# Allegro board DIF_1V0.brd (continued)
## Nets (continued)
IO_PRE_3.3_1: R160.2 U3.R2(IO_L3N_T0_DQS_34)
IO_PRE_3.3_2: R158.1 U3.R3(IO_L3P_T0_DQS_34)
IO_PRE_3.3_3: R156.2 U3.R4(IO_L13P_T2_MRCC_34)
IO_PRE_3.3_4: R154.1 U3.T4(IO_L13N_T2_MRCC_34)
IO_PRE_3.3_5: R152.2 U3.T1(IO_L1P_T0_34)
IO_PRE_3.3_6: R150.1 U3.T3(IO_0_34)
IO_PRE_3.3_7: R148.2 U3.U1(IO_L1N_T0_34)
IO_PRE_3.3_8: R146.1 U3.U3(IO_L6P_T0_34)
IO_PRE_3.3_9: R144.2 U3.Y1(IO_L5N_T0_34)
IO_PRE_3.3_10: R138.1 U3.V3(IO_L6N_T0_VREF_34)
IO_PRE_3.3_11: R111.2 U3.Y2(IO_L4N_T0_34)
IO_PRE_3.3_12: R118.1 U3.V5(IO_L16N_T2_34)
IO_PRE_3.3_13: R130.1 U3.V4(IO_L12P_T1_MRCC_34)
IO_PRE_3.3_14: R132.2 U3.V2(IO_L2N_T0_34)
IO_PRE_3.3_15: R134.1 U3.W1(IO_L5P_T0_34)
IO_SMA1: R19.2 U3.B21(IO_L21P_T3_DQS_16)
IO_SMA2: R26.2 U3.A21(IO_L21N_T3_DQS_16)
IO_SMA3: R30.2 U3.B15(IO_L7P_T1_16)
IO_SMA4: R28.2 U3.G13(IO_L1N_T0_AD0N_15)
IO_SMA5: R32.2 U3.G15(IO_L2P_T0_AD8P_15)
M2: J8.2 U3.U9(M2_0)
OUT_CK_5N_1: R69.1 R70.1 R81.2
OUT_CK_5P_1: R68.2 R69.2 R79.2
OUT_CK_40N_1: R97.1 R108.1 R115.1
OUT_CK_40P_1: R84.1 R95.2 R108.2
OUT_DATA_2+: U8.2(TX1_P) U8.14(TX2_P) U10.2(1Y)
OUT_DATA_2-: U8.3(TX1_N) U8.15(TX2_N) U10.3(1Z)
OUT_DATA_3+: U8.11(RX2_P) U8.23(RX1_P) U10.6(2Y)
OUT_DATA_3-: U8.10(RX2_N) U8.22(RX1_N) U10.5(2Z)
OUT_DATA_4+: U9.6(D_P A) U9.18(D_P B) U10.10(3Y)
OUT_DATA_4-: U9.7(D_N A) U9.19(D_N B) U10.11(3Z)
OUT_RAZ_CHN_N_1: R85.1 R90.1 R93.2
OUT_RAZ_CHN_P_1: R82.2 R85.2 R102.2
OUT_RX_HV: U3.AA5(IO_L10P_T1_34) U6.3(RXD)
OUT_TRIG_EXT_N_1: R75.1 R76.1 R101.1
OUT_TRIG_EXT_P_1: R74.2 R75.2 R89.1
OUT_VAL_EVT_N_1: R72.1 R73.1 R88.2
OUT_VAL_EVT_P_1: R71.2 R72.2 R98.2
PROGRAM_B: R43.1 SW2.2 U3.N12(PROGRAM_B_0)
REFCLK+: C1.1 O1.4(OUT+) R1.1
REFCLK-: C5.1 O1.5(OUT-) R1.2
RESET#: C115.1 R65.1 U12.49(RESETN) U15.2
RX_VCCP_0: C128.1 C129.1 C130.1 DU1.15(VCCR) L5.1
SCL: R63.1 U12.22(SCL) U14.6(SCL)
SDA: R64.1 U12.23(SDA) U14.5(SDA)
SFP_RS0: DR14.1 DR15.1 DU1.7(RS0)
SFP_RS1: DR12.1 DR13.1 DU1.9(RS1)
TRG_EXT: R22.2 U3.A13(IO_L10P_T1_16)
TX_VCCP_0: C121.1 C122.1 C123.1 DU1.16(VCCT) L4.1
USB_CLKOUT: R52.1 U3.Y18(IO_L13P_T2_MRCC_14)
USB_FD0: U3.W22(IO_L7N_T1_D10_14) U12.25(PB0/FD0)
USB_FD1: U3.T21(IO_L4P_T0_D04_14) U12.26(PB1/FD1)
USB_FD2: U3.R17(IO_L24N_T3_A00_D16_14) U12.27(PB2/FD2)
USB_FD3: U3.P16(IO_L24P_T3_A01_D17_14) U12.28(PB3/FD3)
USB_FD4: U3.T18(IO_L20N_T3_A07_D23_14) U12.29(PB4/FD4)
USB_FD5: U3.R18(IO_L20P_T3_A08_D24_14) U12.30(PB5/FD5)
USB_FD6: U3.U21(IO_L4N_T0_D05_14) U12.31(PB6/FD6)
USB_FD7: U3.U18(IO_L18N_T2_A11_D27_14) U12.32(PB7/FD7)
USB_FD8: U3.AB20(IO_L15N_T2_DQS_DOUT_CSO_B_14) U12.52(PD0/FD8)
USB_FD9: U3.AA19(IO_L15P_T2_DQS_RDWR_B_14) U12.53(PD1/FD9)
USB_FD10: U3.AA18(IO_L17P_T2_A14_D30_14) U12.54(PD2/FD10)
USB_FD11: U3.AB18(IO_L17N_T2_A13_D29_14) U12.55(PD3/FD11)
USB_FD12: U3.V17(IO_L16P_T2_CSI_B_14) U12.56(PD4/FD12)
USB_FD13: U3.W17(IO_L16N_T2_A15_D31_14) U12.1(PD5/FD13)
USB_FD14: U3.U17(IO_L18P_T2_A12_D28_14) U12.2(PD6/FD14)
USB_FD15: U3.R16(IO_L22N_T3_A04_D20_14) U12.3(PD7/FD15)
USB_FLAGA: U3.V20(IO_L11N_T1_SRCC_14) U12.36(CTL0/FLAGA)
USB_FLAGB: U3.W20(IO_L12N_T1_MRCC_14) U12.37(CTL1/FLAGB)
USB_FLAGC: R55.2 U3.W21(IO_L7P_T1_D09_14)
USB_FLAGD/SLCS#: U3.Y19(IO_L13N_T2_MRCC_14) U12.47(PA7/FLAGD/SLCSN)
USB_IFCLK: U3.Y22(IO_L9N_T1_DQS_D13_14) U12.20(IFCLK)
USB_PKTEND: U3.AB21(IO_L10P_T1_D14_14) U12.46(PA6/PKTEND)
USB_SLOE: R58.2 U3.Y21(IO_L9P_T1_DQS_14)
USB_SLRD: U3.AB22(IO_L10N_T1_D15_14) U12.8(RDY0/*SLRD)
USB_SLWR: R59.2 U3.W19(IO_L12P_T1_MRCC_14)
USB_WAKEUP: R56.1 U3.AA20(IO_L8P_T1_D11_14)
USB_WU2: R57.1 U3.V19(IO_L14N_T2_SRCC_14)
WU: J13.2 R56.2 U12.51(WAKEUP)
WU2_S: J14.2 R57.2 U12.43(PA3/WU2)
XTALIN: C107.2 U12.12(XTALIN) Y1.1
XTALOUT: C106.2 U12.11(XTALOUT) Y1.2
N00327: C102.1 R48.1 U6.10(VO)
N00500: R49.2 U6.16(TEMP)
N00677: R50.2 U7.3(OUT)
N00715: C105.1 R51.2 U7.4(VDD)
N12323: J7.4(TMS) R38.1
N12327: R38.2 U3.T13(TMS_0)
N12331: R39.2 U3.V12(TCK_0)
N12335: R40.2 U3.U13(TDO_0)
N12339: R41.2 U3.R13(TDI_0)
N12343: J7.6(TCK) R39.1
N12347: J7.8(TDO) R40.1
N12351: J7.10(TDI) R41.1
N12485: U3.AB17(IO_L2N_T0_13) U11.3(DO1)
N12489: U3.AA16(IO_L1N_T0_13) U11.5(DO2)
N12493: U3.AB16(IO_L2P_T0_13) U11.11(DO3)
N12742: U3.AA14(IO_L5N_T0_13) U10.1(1A)
N12746: U3.AB15(IO_L4N_T0_13) U10.7(2A)
N12750: U3.AA15(IO_L4P_T0_13) U10.9(3A)
N13183: D9.1(CATHODE) R47.2
N13221: D10.2(ANODE) R46.1
N15768: DR2.1 DR16.1 DU1.3(TX_DISABLE) U3.A14(IO_L10N_T1_16)
N15772: D12.1(CATHODE) DR1.1 DU1.2(TX_FAULT) U3.B16(IO_L7N_T1_16)
N15776: DR5.1 DU1.4(SDA) U3.B17(IO_L11P_T1_SRCC_16)
N15834: DR6.1 DU1.5(SCL) U3.B13(IO_L8N_T1_16)
N15838: D14.1(CATHODE) DR4.1 DU1.8(LOS) U3.A18(IO_L17P_T2_16)
N16065: C126.2 R66.1 U3.B8(MGTPRXP0_216)
N16069: C120.2 R66.2 U3.A8(MGTPRXN0_216)
N16073: C127.1 U3.B4(MGTPTXP0_216)
N16077: C133.1 U3.A4(MGTPTXN0_216)
N17024: R34.2 U3.F8(MGTRREF_216)
N26834: R114.2 U3.N4(IO_L19P_T3_35)
N27061: R117.1 U3.M5(IO_L23N_T3_35)
N27703: R110.2 U3.N3(IO_L19N_T3_VREF_35)
N27930: R112.1 U3.M2(IO_L16N_T2_35)
N28287: R107.1 U3.N2(IO_L22N_T3_35)
N29233: R123.2 U3.K4(IO_L13P_T2_MRCC_35)
N29237: R125.1 U3.K3(IO_L14N_T2_SRCC_35)
N31078: R71.1 U3.K1(IO_L7P_T1_AD6P_35)
N31082: R73.2 U3.J1(IO_L7N_T1_AD6N_35)
N31695: R68.1 U3.R1(IO_L20P_T3_35)
N31699: R70.2 U3.P1(IO_L20N_T3_35)
N31992: R95.1 U3.M1(IO_L15P_T2_DQS_35)
N31996: R115.2 U3.L1(IO_L15N_T2_DQS_35)
N32289: R74.1 U3.H2(IO_L8P_T1_AD14P_35)
N32293: R76.2 U3.G2(IO_L8N_T1_AD14N_35)
N33117: R82.1 U3.G1(IO_L5P_T0_AD13P_35)
N33121: R90.2 U3.F1(IO_L5N_T0_AD13N_35)
N33886: R105.2 U3.P4(IO_L21N_T3_DQS_35)
N33890: R94.1 U3.P2(IO_L22P_T3_35)
N34550: R91.1 U3.Y7(IO_L23N_T3_34)
N34554: R100.2 U3.AA4(IO_L11N_T1_SRCC_34)
N36552: R96.1 U3.W5(IO_L15N_T2_DQS_34)
N36779: R106.2 U3.AB2(IO_L8N_T1_34)
N37008: R109.1 U3.W6(IO_L15P_T2_DQS_34)
N38396: R104.2 U3.AA3(IO_L9N_T1_DQS_34)
N38400: R103.1 U3.Y6(IO_L18P_T2_34)
N38404: R92.2 U3.AB3(IO_L8P_T1_34)
N38635: R99.1 U3.W7(IO_L19N_T3_VREF_34)
N38992: R87.2 U3.AA6(IO_L18N_T2_34)
N39253: R83.2 U3.AB8(IO_L22N_T3_34)
N39482: R80.1 U3.Y8(IO_L23P_T3_34)
N39711: R78.2 U3.Y9(IO_L24N_T3_34)
N39940: R77.1 U3.W9(IO_L24P_T3_34)
N40729: R113.1 U3.Y4(IO_L11P_T1_SRCC_34)
N40733: R116.2 U3.U5(IO_L14N_T2_SRCC_34)
N41303: R128.2 U3.W2(IO_L4P_T0_34)
N42028: R126.1 U3.AB1(IO_L7N_T1_34)
N42251: R124.2 U3.AA1(IO_L7P_T1_34)
N42476: R120.2 U3.Y3(IO_L9P_T1_DQS_34)
N42480: R122.1 U3.W4(IO_L12N_T1_MRCC_34)
N63573: C5.2 R2.2 U3.E6(MGTREFCLK0N_216)
N64906: C103.1 R48.2 R145.1 R147.2 TP10.1
N64910: C104.1 R49.1 R50.1 R142.1
N65349: C1.2 R2.1 U3.F6(MGTREFCLK0P_216)
N65361: R4.2 U3.U20(IO_L11P_T1_SRCC_14)
N65373: R6.2 R8.1 U3.D19(IO_L14N_T2_SRCC_16)
N71766: R127.2 U3.L4(IO_L18N_T2_35)
N72632: R141.1 U3.J4(IO_L13N_T2_MRCC_35)
N73220: R119.2 U3.M3(IO_L16P_T2_35)
N73812: R86.1 U3.AA8(IO_L22P_T3_34)
N179918: R163.2 R165.1 U16.16(FB/SNS)
N180887: R170.2 R172.1 U19.16(FB/SNS)
N181938: R181.2 R183.1 U20.16(FB/SNS)
N182899: R164.2 R166.1 U17.16(FB/SNS)
N183888: R171.2 R173.1 U18.16(FB/SNS)
N606190: C3.2 C4.2 L1.2 U1.4(VCC)
N606320: R4.1 U1.3(OUT)
N607489: R9.1 U2.4(PFI)
N607623: R5.1 SW1.2 U2.1(/MR)
N607665: R8.2 R10.2 U2.7(/RESET)
N1798468: R167.1 U16.9(PG)
N1808198: R174.1 U19.9(PG)
N1818788: R186.1 U20.9(PG)
N1828438: R168.1 U17.9(PG)
N1838328: R175.1 U18.9(PG)
N15089767: O1.1(ST/OE) R3.1
N15104211: J8.3 R42.2
N15135333: D1.2(ANODE) R11.2
N15135363: D2.2(ANODE) R12.2
N15135433: D3.2(ANODE) R13.2
N15135465: D4.2(ANODE) R14.2
N15135513: D5.2(ANODE) R15.2
N15135593: D6.2(ANODE) R16.2
N15135681: D7.2(ANODE) R17.2
N15135745: D8.2(ANODE) R18.2
N15136939: J2.1 R21.1 R23.1
N15136999: R21.2 U4.3(VP)
N15137097: R24.1 R25.1 U4.4(VN)
N15137609: J1.1 R19.1 R20.1
N15137848: J3.1 R26.1 R27.1
N15138095: J5.1 R30.1 R31.1
N15138348: J4.1 R28.1 R29.1
N15138605: J6.1 R32.1 R33.1
N16764512: R190.2 R191.1 U21.16(FB/SNS)
N16766730: D18.2(ANODE) R185.2
N16766909: D19.2(ANODE) R187.2
N16767511: D21.2(ANODE) R189.2
N16767909: D17.2(ANODE) R184.2
N16777633: R52.2 U12.5(CLKOUT)
N16778120: J15.2 R62.1 U14.1(A0)
N16778188: U12.16(DMINUS) U13.2(D-)
N16778190: U12.15(DPLUS) U13.3(D+)
N16778248: R53.2 U12.21(RESERVED)
N16778864: D16.1(ANODE) R194.2
N16779811: DR12.2 DR17.2
N16779911: DR14.2 DR18.2
N16782519: D11.1(ANODE) R54.1
N16783572: J16.B2 R78.1
N16783577: J16.B4 R83.1
N16783581: J16.B6 R87.1
N16783585: J16.B8 R100.1
N16783590: J16.B10 R92.1
N16783594: J16.B12 R104.1
N16783598: J16.B14 R106.1
N16783603: J16.B16 R111.1
N16783607: J16.B18 R116.1
N16783611: J16.B20 R120.1
N16783616: J16.B22 R124.1
N16783620: J16.B24 R128.1
N16783624: J16.B26 R132.1
N16783629: J16.B28 R136.1
N16783633: J16.B30 R140.1
N16783637: J16.B32 R144.1
N16783642: J16.B34 R148.1
N16783646: J16.B36 R152.1
N16783650: J16.B38 R156.1
N16783654: J16.B40 R160.1
N16789956: J17.A3 R84.2
N16789966: J17.A7 R89.2
N16789976: J17.A11 R94.2
N16789981: J17.A13 R107.2
N16789986: J17.A15 R112.2
N16789991: J17.A17 R117.2
N16789996: J17.A19 R121.2
N16790001: J17.A21 R125.2
N16790006: J17.A23 R129.2
N16790016: J17.A27 R137.2
N16790021: J17.A29 R141.2
N16790026: J17.A31 R145.2
N16790031: J17.A33 R149.2
N16790036: J17.A35 R153.2
N16790041: J17.A37 R157.2
N16790052: J17.A39 R161.2
N16790060: J17.B2 R81.1
N16790070: J17.B6 R88.1
N16790080: J17.B10 R93.1
N16790085: J17.B12 R105.1
N16790090: J17.B14 R110.1
N16790095: J17.B16 R114.1
N16790100: J17.B18 R119.1
N16790105: J17.B20 R123.1
N16790110: J17.B22 R127.1
N16790120: J17.B26 R135.1
N16790130: J17.B30 R143.1
N16790135: J17.B32 R147.1
N16790140: J17.B34 R151.1
N16790145: J17.B36 R155.1
N16790150: J17.B38 R159.1
N16790155: J17.B40 R162.1
N16838243: J17.A4 R97.2
N16838862: J17.B5 R98.1
N16839386: J17.A8 R101.2
N16839910: J17.B9 R102.1
N16840818: J17.A26 R139.2
N16841427: J17.B25 R133.1
N16841941: J17.A24 R131.2
N17984614: C140.1 U16.15(SS)
N18081914: C148.1 U19.15(SS)
N18187814: C157.1 U20.15(SS)
N18284314: C141.1 U17.15(SS)
N18383214: C149.1 U18.15(SS)
N151370452: R22.1 U4.1(Q)
N167617330: J18.1 R178.1
N167617332: J18.3 R179.1
N167644448: R192.1 U21.9(PG)
N167671021: D20.2(ANODE) R188.2
N167776730: R55.1 U12.38(CTL2/FLAGC)
N167776810: R58.1 U12.42(PA2/SLOE)
N167776910: R59.1 U12.9(RDY1/*SLWR)
N167800060: D12.2(ANODE) DR9.1
N167800300: D13.2(ANODE) DR10.1
N167800460: D14.2(ANODE) DR11.1
N167801340: DR7.1
N167801341: DR8.1
N167815100: R54.2 U13.1(V)
N167837560: J16.A1 R77.2
N167837562: J16.A3 R80.2
N167837564: J16.A5 R86.2
N167837566: J16.A7 R99.2
N167837568: J16.A9 R91.2
N168028960: J13.1 R60.1
N168030100: J14.1 R61.1
N1676444414: C161.1 U21.15(SS)
N1678375610: J16.A11 R103.2
N1678375612: J16.A13 R96.2
N1678375614: J16.A15 R109.2
N1678375616: J16.A17 R113.2
N1678375618: J16.A19 R118.2
N1678375620: J16.A21 R122.2
N1678375622: J16.A23 R126.2
N1678375624: J16.A25 R130.2
N1678375626: J16.A27 R134.2
N1678375628: J16.A29 R138.2
N1678375630: J16.A31 R142.2
N1678375632: J16.A33 R146.2
N1678375634: J16.A35 R150.2
N1678375636: J16.A37 R154.2
N1678375638: J16.A39 R158.2
N1679025740: J17.B1 R79.1

Pads without a net: J7 12 14; O1 2; U1 1; U2 5 6 8; U3 A6 A10 A15 A16 A19 AA9 AA10 AA11 AA13 AB6 AB7 AB10 AB11 AB12 AB13 B6 B10 B18 B20 B22 C5 C7 C9 C11 C13 C14 C15 C17 C18 C19 C20 D5 D7 D9 D11 D14 D15 D16 D17 D20 D22 E10 E13 E14 E16 E17 E18 E19 F3 F10 F13 F14 F15 F16 F18 F19 F21 G4 G16 G17 G18 G20 H3 H4 H5 H13 H14 H15 H17 H18 H19 H20 H22 J2 J5 J6 J14 J15 J16 J17 J19 J20 J21 J22 K6 K13 K14 K16 K17 K18 K19 K21 K22 L3 L5 L6 L13 L14 L15 L16 L18 L19 L20 L21 M6 M13 M15 M16 M17 M18 M20 M21 M22 N5 N13 N14 N15 N17 N18 N19 N20 N22 P5 P6 P14 P15 P17 P19 P20 R6 R14 R19 T5 T6 T14 T15 T16 T20 U2 U6 U7 U15 U16 V7 V8 V9 V10 V13 V14 V15 V22 W10 W11 W12 W14 W15 W16 Y11 Y12 Y13 Y14 Y16 Y17; U5 3 4 5 6 11 12 13 14; U6 6 7 9 11 12 13 14; U8 4 5 8 9 16 17 20 21; U9 4 5 8 9 16 17 20 21; U10 13 14 15; U11 13 14 15; U12 40 41; U13 4; U16 2 3 4 13 14 17; U17 2 3 4 13 14 17; U18 2 3 4 13 14 17; U19 2 3 4 13 14 17; U20 2 3 4 13 14 17; U21 2 3 4 13 14 17

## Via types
v1: diameter 0.305, hole 0.203, TOP to BOTTOM, 310 vias
v2: diameter 0.457, hole 0.203, TOP to BOTTOM, 839 vias
v3: diameter 0.711, hole 0.406, TOP to BOTTOM, 26 vias
v4: diameter 1.016, hole 0.61, TOP to BOTTOM, 4 vias
v5: diameter 2.032, hole 1.524, TOP to BOTTOM, 1 via
v6: diameter 1.524, hole 1.016, TOP to BOTTOM, 9 vias

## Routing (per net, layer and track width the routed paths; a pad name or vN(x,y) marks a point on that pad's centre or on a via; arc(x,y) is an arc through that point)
1.0V: length 39.5
  TOP w0.102: v1(95.63,60.17) 95.17,59.71 U3.F7 ; v1(96.7,61.29) 97.15,60.84 U3.D6
  TOP w0.152: U3.N11 v1(87.69,56.17) ; U3.K8 v1(91.62,59.17) ; U3.N7 v1(87.69,60.17) ; U3.T8 v1(84.69,59.17) ; U3.R7 v1(85.69,60.17) ; U3.J11 v1(92.62,56.17) ; U3.L11 v1(90.62,56.17) ; v1(97.64,57.2) 97.15,56.72 U3.D10 ; U3.L7 v1(90.62,60.17) ; U3.H8 v1(93.62,59.17) ; U3.J9 v1(92.62,58.17) ; U3.H10 v1(93.62,57.17) ; U3.T10 v1(84.69,57.17) ; U3.J7 v1(92.62,60.17) ; U3.R9 v1(85.69,58.17) ; U3.M8 v1(88.69,59.17) ; U3.P8 v1(86.69,59.17) ; U3.E8 96.15,58.71 v1(95.73,58.29) 95.15,57.71 U3.F9 ; U3.P10 v1(86.69,57.17)
  TOP w0.305: UNK1.0V1.1 26.26,32.64 R184.1
  TOP w0.61: 15.09,32.98 R193.2 ; R193.2 15.09,34.23 ; R193.2 14.5,33.6
  BOTTOM w0.152: v1(84.69,57.17) 84.28,57.58 C88.1 ; v1(95.63,60.17) 95.12,59.66 C68.1 ; v1(95.63,60.17) 95.94,59.87 C66.1 ; v1(95.63,60.17) 95.15,60.66 C38.1 ; C76.1 97.16,56.72 v1(97.64,57.2) 98.07,56.77 C44.1 ; v1(87.69,56.17) 87.68,56.17 C74.1 ; v1(92.62,56.17) 92.15,56.64 C78.1 ; v1(101.52,57.18) 101.42,57.28 C37.1 ; C86.1 84.31,58.8 v1(84.69,59.17) ; C77.1 92.18,60.61 v1(92.62,60.17) ; v1(93.62,57.17) 93.34,57.45 C73.1 ; C72.1 86.23,57.63 v1(86.69,57.17) ; v1(88.69,59.17) 89.19,58.67 C75.1 ; v1(86.69,59.17) 86.92,58.94 C85.1 ; v1(96.7,61.29) 97.03,61.62 C65.1 97.08,61.75 C42.1 ; v1(91.62,59.17) 91.54,59.25 C69.1 ; v1(87.69,60.17) 88.2,59.66 C70.1 ; C67.1 95.89,58.14 v1(95.73,58.29) 95.83,58.39 C40.1 ; v1(85.69,60.17) 85.57,60.06 C71.1 ; v1(90.62,56.17) 90.12,56.67 90.04,56.67 ; C39.1 v1(101.57,55.73) ; C36.1 v1(97.64,60.22)
  BOTTOM w0.203: v2(103.61,60.07) 103.35,59.82 C41.1
  vias: v2(12.34,35.13) v2(12.4,33.76) v2(12.4,32.69) v2(13.59,35.15) v2(13.72,33.81) v2(13.74,32.69)
1.0V_OUT: length 15.8
  TOP w0.305: R171.1 18.16,32.46 18.47,32.16 U18.18
  TOP w0.508: C145.1 13.13,30 ; 13.13,30 14.53,30 ; 13.13,30 14.22,31.09 ; U18.20 U18.19 U18.18 ; U18.20 16.52,31.71 ; U18.20 17.17,32.42 ; U18.1 16.12,31.23
  TOP w0.61: 17.58,33.22 R171.1 18.16,33.85 ; R193.1 16.61,34.23 ; R193.1 16.61,32.98 ; R193.1 17.2,33.6
  BOTTOM w0.305: R175.2 19.71,29.72 17.1,32.33 v2(16.33,32.33)
1.2V: length 12.2
  TOP w0.102: U3.C4 98.15,62.71 v1(98.68,62.18) 99.15,61.71 U3.B5
  TOP w0.152: v1(99.64,56.18) 99.17,55.71 U3.B11 ; U3.C8 98.18,58.71 v1(98.63,59.16) 99.15,59.68 U3.B7 ; v1(99.62,57.23) 99.15,57.69 U3.B9
  TOP w0.203: UNK1.2V1.1 15.88,58.45 R189.1
  TOP w0.61: 5.46,64.5 R182.2 5.46,63.26
  BOTTOM w0.152: C47.1 v1(102.23,66.9) ; C48.1 99.09,58.7 v1(98.63,59.16) ; R34.1 v1(102.11,62.36) ; v1(98.68,62.18) 99.36,61.49 C46.1 ; C49.1 v1(102.06,65.35)
  vias: v2(4.47,64.87) v2(4.47,62.59) v2(5.16,67.16) v2(5.18,66.42) v2(5.16,65.71) v2(5.23,62.28) v2(5.18,61.16)
1.2V_OUT: length 16.5
  TOP w0.381: U17.18 10.08,62.05 9.8,62.33 ; U17.19 9.43,62.34 ; U17.1 7.73,61.2
  TOP w0.508: U17.20 U17.19 U17.18
  TOP w0.61: 8.78,62.23 U17.20 8.43,61.53 ; 11.07,65.13 C137.1 ; C137.1 9.75,66.32 ; C137.1 12.4,66.32 ; R182.1 6.99,64.5 ; R182.1 7.57,63.88 ; R182.1 6.99,63.26 ; 9.58,63.35 R164.1 ; R164.1 10.16,62.73 ; R164.1 10.16,63.97
  BOTTOM w0.305: v3(8.59,63.09) 10.72,60.96 R168.2
1.8V: length 12.9
  TOP w0.152: U3.P12 v1(86.69,54.25) ; U3.M12 v1(88.69,54.25) ; U3.R11 v1(85.69,56.17) ; U3.H12 v1(93.62,54.25) ; U3.K12 v1(91.62,54.25)
  TOP w0.305: R188.1 13.26,9.14 UNK1.8V1.1
  TOP w0.61: 8.53,20.95 R180.2 9.12,21.58
  BOTTOM w0.152: v1(86.69,54.25) 87.27,53.66 C80.1 ; C82.1 91.62,54.24 v1(91.62,54.25) 91.32,54.25 90.42,55.14 L2.2 ; C81.1 93.62,54.25 v1(93.62,54.25) ; C84.1 88.7,54.25 v1(88.69,54.25) 89.24,53.7 C83.1 ; v1(85.69,56.17) 85.24,56.62 C79.1
  vias: v2(4.83,23.5) v2(4.9,22.4) v2(4.9,21.06) v2(6.76,21.18) v2(6.99,23.55) v2(6.96,22.45) v2(8.84,23.57) v2(8.97,22.4)
1.8V_OUT: length 15.8
  TOP w0.508: U20.19 12.13,19.9 ; U20.19 U20.20 11.48,19.89 ; U20.19 U20.18 ; U20.1 10.43,18.48
  TOP w0.61: 10.64,20.33 R180.1 ; R180.1 11.23,20.95 ; R180.1 10.64,21.58 ; 11.58,20.95 R181.1 ; R181.1 12.17,21.58 ; R181.1 12.17,20.33 ; C153.1 6.81,19.51 ; C153.1 6.81,17.12 ; C153.1 5.49,18.31 ; C153.1 8.13,18.31
  BOTTOM w0.203: v2(12.55,20.02) 14.17,18.39 R186.2
2.5V: length 22.5
  TOP w0.102: v1(92.63,53.21) 92.15,53.69 U3.J13 ; U3.H6 93.15,60.72 v1(93.65,61.21)
  TOP w0.152: v1(92.71,50.27) 93.15,50.71 U3.H16 ; v1(89.61,63.14) 89.18,62.71 U3.M4 ; U3.F2 95.16,64.71 v1(95.63,65.18) ; U3.G19 v1(94.62,47.25) ; v1(92.61,64.16) 92.16,63.71 U3.J3 ; U3.N1 v1(88.15,66.38) ; U3.K20 v1(91.62,46.25) ; v1(89.69,49.25) 90.15,49.71 U3.L17 ; U3.N21 v1(87.69,45.25) ; U3.C1 v1(98.15,66.36)
  TOP w0.508: UNK2.5V1.1 30.63,40.01 R187.1 ; R177.2 v4(19.91,44.42)
  BOTTOM w0.152: v1(91.62,46.25) 91.6,46.23 C13.1 ; C25.1 88.8,62.33 v1(89.61,63.14) ; v1(98.15,66.36) 98.58,65.94 C27.1 ; C10.1 92.46,50.52 v1(92.71,50.27) ; v1(92.63,53.21) 93.09,53.67 C9.1 ; C24.1 92.15,63.7 v1(92.61,64.16) ; v1(94.62,47.25) 94.28,47.58 C12.1 ; C23.1 88.14,66.37 v1(88.15,66.38) 88.15,66.11 87.55,65.51 C28.1 ; v1(93.65,61.21) 93.24,61.62 C26.1 ; v1(87.69,45.25) 87.33,45.61 C14.1 ; C11.1 90.02,48.92 v1(89.69,49.25)
2.5V_OUT: length 16.3
  TOP w0.305: U19.19 24.17,43.46 24.59,43.88 R170.1 23.9,45.54 v3(23.44,45.54)
  TOP w0.508: U19.20 U19.19 U19.18 ; U19.20 22.68,43.85 R177.1 ; U19.20 U19.1
  BOTTOM w0.305: R174.2 25.73,43.26 v3(23.44,45.54) 24.54,46.63 C144.1
3.3V: length 153
  TOP w0.102: U3.E15 96.16,51.71 v1(96.7,52.25)
  TOP w0.152: U3.AA17 v1(80.66,50.22) ; R42.1 v2(63.2,60.81) ; DR11.2 v2(113.18,42.7) ; U3.AA7 80.15,59.73 v1(79.68,60.2) ; U3.F22 v1(95.15,43.97) ; R46.2 v2(64.9,58.95) ; U3.W3 82.11,63.71 v1(81.66,64.16) ; U3.V6 83.15,60.74 v1(82.68,61.21) ; U3.AB14 78.87,52.43 v1(78.46,52.43) ; U3.T22 v1(85.15,44.15) ; v1(84.63,65.2) 85.12,64.71 U3.T2 ; U4.5 v2(113.08,55.14) ; U3.U19 v1(83.69,47.25) ; v1(86.66,62.23) 86.15,61.72 U3.R5 ; U3.U11 84.15,55.7 v1(84.63,55.22) ; U3.Y20 v1(80.69,46.25) ; U3.W13 82.16,53.71 v1(82.68,54.23) ; U3.AB4 v1(78.38,62.71) ; DR10.2 v2(112.22,43.51) ; U3.D18 v1(97.62,48.25) ; v1(95.63,54.23) 95.15,54.71 U3.F12 ; v1(83.65,58.2) 84.15,58.7 U3.U8 ; U3.T12 85.16,54.71 v1(85.62,55.17) ; U3.B14 99.16,52.71 v1(99.67,52.2) ; U3.V16 v1(82.69,50.25) ; R35.2 v2(84.12,26.24) ; U3.R15 v1(85.69,51.25) ; v1(80.75,57.15) 81.15,56.74 U3.Y10 ; U3.M14 v1(88.69,52.25) ; R25.2 v2(108.81,55.58) ; DR9.2 v2(112.27,45.92) ; U3.A17 v2(100.81,49.71) ; U3.C21 v1(98.62,45.25) ; R5.2 v2(94.84,9.63) ; U3.P18 v1(86.69,48.25)
  TOP w0.203: UNK3.3V2.1 31.42,62.84 R185.1 ; U12.18 v2(70.83,11.77) ; v2(63.84,23.9) U12.50 63.84,21.68 v2(63.73,21.56) ; R64.2 v2(87.78,8.89) ; C113.2 63.2,11.61 v2(63.21,11.62) U12.6 ; R43.2 v2(109.5,36.83) ; 56.46,11.71 v4(56.54,11.79) ; R63.2 v2(87.78,11.89) ; R61.2 v2(68.91,33.35) ; v2(62.36,34.11) 62.99,34.75 R60.2 ; U12.24 v2(74.64,14.11)
  TOP w0.381: U12.39 70.83,21.09 ; U12.34 74,21.15
  TOP w0.508: 57.33,10.06 C114.2 56.46,10.69 ; U5.2 88.98,22.96 ; 42.88,17.88 41.3,17.88 ; 42.88,17.88 U11.16 ; 42.88,17.88 v2(42.04,17.04) ; U10.4 v2(31.01,21.82) ; 18.95,65.28 R176.2 17.58,63.83 ; U11.4 48.03,21.69 ; R62.2 98.37,17.45 ; C57.1 89.89,21.69
  TOP w0.61: 34.91,26.7 C164.2 ; C164.2 36.16,26.7 ; C164.2 35.53,26.11 ; C58.1 95.83,22.91 ; C58.1 95.83,20.68 ; C58.1 94.82,21.79 ; 37.96,25.63 U10.16 35.53,26.05
  BOTTOM w0.152: v1(84.63,65.2) 84.89,65.46 C30.1 ; C33.1 79.63,60.15 v1(79.68,60.2) ; C16.1 96.16,51.71 v1(96.7,52.25) ; C60.1 84.99,54.86 v1(84.63,55.22) ; C29.1 78.23,62.56 v1(78.38,62.71) ; C99.1 84.22,47.78 v1(83.69,47.25) 84.3,46.63 C98.1 ; C94.1 80.47,52.48 78.51,52.48 v1(78.46,52.43) 78.08,52.04 C91.1 ; C20.1 95.33,44.15 v1(95.15,43.97) ; v1(98.62,45.25) 98.7,45.33 C19.1 ; R10.1 v2(110.26,26.59) ; v1(82.69,50.25) 82.22,50.71 C92.1 ; v2(72.57,55.07) 72.11,55.52 R45.2 ; v1(80.75,57.15) 80.24,56.64 C89.1 ; v2(103.28,33.07) 103,32.79 C7.1 ; v1(82.68,61.21) 83.08,60.81 C32.1 83.29,60.58 v1(83.69,60.17) 83.49,59.97 C61.1 ; v1(85.69,51.25) 85.47,51.46 C96.1 ; C90.1 82.65,54.2 v1(82.68,54.23) ; v2(96.42,39.27) 95.63,38.48 R36.2 ; v2(99.06,34.9) 99.75,34.21 R9.2 ; v1(99.67,52.2) 99.26,52.6 C15.1 ; v1(81.66,64.16) 81.61,64.21 C34.1 ; R37.2 v2(91.64,26.82) ; v1(80.66,50.22) 80.33,49.89 C93.1 ; C97.1 87.18,47.75 v1(86.69,48.25) ; C31.1 86.16,61.72 v1(86.66,62.23) ; v1(95.63,54.23) 95.78,54.38 C59.1 ; v1(97.62,48.25) 97.35,48.51 C18.1 ; R44.2 v2(102.39,55.96) ; C17.1 100.73,49.63 v2(100.81,49.71) ; v1(88.69,52.25) 89.13,51.8 C95.1
  BOTTOM w0.203: C112.2 71.73,10.87 v2(70.83,11.77) ; DR4.2 v2(132.28,33.1) ; C2.2 v2(92.71,36.07) ; C21.1 113.18,55.04 v2(113.08,55.14) 113.16,55.22 113.16,56.11 ; DR18.1 v2(140.82,41.22) ; 30.53,22.25 30.45,22.17 ; C131.1 v2(135.74,51.87) ; DR17.1 v2(140.74,31.67) ; DR1.2 v2(127.53,33.05) ; v2(74.64,14.11) 74.63,14.12 C111.2 ; v2(63.84,23.9) 63.84,24.3 C108.2 ; DR3.2 v2(130.68,33.05) ; DR6.2 v2(131.47,40.97) ; v2(128.07,42.31) 128.07,42.24 DR2.2 ; DR5.2 v2(129.08,33.02) ; R65.2 v2(86.16,22.45)
  BOTTOM w0.305: L5.2 v3(132.69,43.81)
  BOTTOM w0.381: C167.2 54.71,20.93 54.08,20.29 ; C167.2 53.8,21.23 ; C167.2 54.71,21.46 54.13,22.05
  BOTTOM w0.508: L4.2 130.14,53.16 130.85,52.45 ; 116.71,65.68 117.07,65.68 ; 116.71,65.68 117.65,66.62 ; 116.71,65.68 O1.6 ; 117.07,65.68 117.86,64.9 ; 117.07,65.68 118.24,65.68 ; C132.1 131.04,56.52 ; 131.04,56.52 130.94,56.52 ; 131.04,56.52 129.92,55.4 ; C110.2 75.26,20.12 ; C165.2 30.07,21.82 ; C165.2 29.16,22.45 ; C165.2 29.16,21.16 ; L3.1 v4(56.54,11.79) ; R3.2 122.99,68.12 ; C6.1 118.52,68.15 ; 130.94,56.52 129.82,56.52 ; 130.94,56.52 129.97,57.48 ; U2.2 98.55,28.04 ; C125.1 130.99,52.45
  BOTTOM w0.61: 117.53,68.77 C6.1 117.53,67.53 ; 70.22,20.52 C109.2 ; C109.2 70.84,21.11 ; C109.2 71.46,20.52 ; 128.54,53.16 L4.2 129.54,54.04 ; C166.2 43,18.76 ; C166.2 43.59,18.14 ; C166.2 43,17.51 ; 96.99,28.73 C8.1 ; C8.1 97.61,28.14 ; C8.1 98.23,28.73 ; 122,68.75 R3.2 122,67.5 ; L1.1 88.57,37.16 ; L1.1 88.57,35.53 ; L1.1 87.88,36.35 ; 140.69,55.48 C124.1 139.57,56.48
  vias: v2(16.94,67.67) v2(17.02,66.42) v2(17.09,65.02) v2(18.36,67.67) v2(18.39,66.4) v2(31.6,21.54) v2(33.71,26.72) v2(34.32,26.24) v2(37.21,26.75) v2(38.05,26.75) v2(39.88,16.51) v2(42.44,16.66) v2(43.21,16.46) v2(43.99,16.51) v2(44.73,16.48) v2(47.73,21.51) v2(47.68,20.37) v2(47.75,22.4) v2(53.64,21.69) v2(54.23,22.58) v2(54.28,19.84) v2(70.13,21.11) v2(70.15,20.37) v2(73.2,21.39) v2(73.84,20.65) v2(73.76,20.04) v2(74.4,20.65) v2(74.57,20.04) v2(88.29,22.66) v2(88.37,32.56) v2(88.42,31.62) v2(89.05,32.56) v2(89.05,31.62) v2(89.08,21.95) v2(89.08,21.03) v2(89.76,22.76) v2(89.84,21.06) v2(94.44,19.81) v2(94.46,18.62) v2(95.58,19.79) v2(95.71,18.64) v2(95.78,26.31) v2(95.91,28.65) v2(95.91,27.51) v2(96.39,17.98) v2(97.56,17.98) v2(97.66,27.43) v2(97.69,26.52) v2(97.71,25.37) v2(98.7,25.4) v2(118.77,69.06) v2(118.85,66.75) v2(118.85,65.71) v2(123.44,65.53) v2(123.6,69.22) v2(123.6,67.18) v2(127.18,55.6) v2(127.15,54.84) v2(128.04,55.68) v2(128.04,53.19) v2(128.07,54.43) v2(129.03,57.12) v2(129.11,56.34) v2(129.11,55.65) v2(129.11,54.84) v2(138.33,56.46) v2(138.35,55.02) v2(139.14,54.48) v2(141.07,54.28)
3.3V_OUT: length 8.1
  TOP w0.305: v3(21.77,63.22) 22.2,62.79 22.2,62.32 U16.18
  TOP w0.381: U16.1 19.77,61.58
  TOP w0.508: U16.18 U16.19 U16.20 20.47,62.59 R176.1
  BOTTOM w0.305: R167.2 23.19,61.8 v3(21.77,63.22)
3.3V_OUT_DET: length 19.7
  TOP w0.203: R157.1 129.92,89.33 v2(129.36,88.77) ; R161.1 v2(131.55,88.93)
  TOP w0.508: U21.20 U21.19 U21.18 7.01,81.71 R190.1 ; U21.1 4.66,80.02
  TOP w0.61: 6.71,81.39 R190.1 ; R190.1 6.71,82.64 ; R190.1 6.12,82.02 ; C159.1 4.09,85.42 ; C159.1 1.7,85.42 ; C159.1 2.9,84.1 ; 5.71,80.62 U21.20 5.36,79.92
  BOTTOM w0.203: R162.2 v2(132.82,89) ; R159.2 v2(130.33,88.8)
  BOTTOM w0.305: v3(4.72,81.03) 7.34,78.41 R192.2
  vias: v2(2.21,82.91) v2(2.21,82.12) v2(2.24,81.15) v2(3.2,82.91) v2(3.25,82.14) v2(3.28,81.23) v2(4.04,81.2) v2(4.06,82.91) v2(4.09,82.14)
5.0V_HV: length 26.2
  TOP w0.152: R140.2 v2(56.41,88.32) ; R136.2 v2(53.82,88.27)
  TOP w0.203: TP9.1 32.69,84.41 U6.1 33.31,83.48 34.75,82.04 C101.2
  TOP w0.305: R51.1 v3(10.08,86.36)
  TOP w0.508: U21.10 8.83,75.22 ; C160.1 9.04,73.74 ; U21.6 U21.7 U21.8 ; U21.5 4.66,75.76 ; U21.11 9.36,75.73
  TOP w0.61: 2.77,75.93 C158.1 ; C158.1 3.35,76.56 ; C158.1 2.77,77.18 ; 5.71,74.52 U21.6 5.36,75.22
  TOP w1.524: L7.2 v2(2.87,58.72)
  BOTTOM w0.508: C154.1 2.84,60.68
  BOTTOM w0.61: 2.87,67.41 C155.1 ; C155.1 1.55,68.61 ; C155.1 4.19,68.61 ; 3.47,61.47 C154.1 2.22,61.47
  vias: v2(1.5,62.13) v2(1.6,66.45) v2(1.7,60.33) v2(1.68,59.49) v2(1.68,58.01) v2(1.75,65.02) v2(3.43,66.42) v2(3.38,64.97) v2(3.53,77.83) v2(3.68,75.26) v2(4.29,60.2) v2(4.32,58.95) v2(4.42,75.26) v2(4.42,74.5) v2(4.98,68.66) v2(8.97,74.3) v2(9.63,74.27) v2(9.65,74.8)
+5VIN: length 21.4
  TOP w0.203: R194.1 v2(12.09,48.01)
  TOP w0.61: 3.12,41.99 J18.2 ; J18.2 4.7,40.41 ; J18.2 6.27,41.99 ; L6.1 15.11,41.25 ; L6.1 13.35,40.31 ; L6.1 15.11,39.37 ; L6.1 16.88,40.31
  TOP w1.524: L7.1 v5(2.87,49.53)
  BOTTOM w0.61: 4.7,40.41 J18.2 ; J18.2 6.27,41.99 ; J18.2 4.7,43.56 ; 9.3,38.65 R179.2 9.3,37.4
  BOTTOM w1.016: R179.2 v2(11.3,38.02)
  vias: v2(7.04,41.45) v2(7.04,40.13) v2(7.09,43) v2(9.02,42.98) v2(9.22,39.42) v2(9.3,41.38) v2(9.27,40.77) v2(9.27,40.16) v2(9.37,35.41) v2(10.54,36.73) v2(10.52,35.41) v2(10.64,41.35) v2(10.64,40.41) v2(10.67,39.45) v2(10.97,42.95) v2(11.3,36.17) v2(11.96,41.3) v2(13.41,37.39) v2(16.18,37.44)
AVCC: length 22
  TOP w0.203: v2(68.28,14.1) 68.28,12.92 U12.14 v2(68.29,11.24) ; v2(65.75,11.77) U12.10 v2(65.75,14.34)
  BOTTOM w0.203: 65.19,10.41 65.75,10.97 v2(65.75,11.77) ; 65.19,10.41 67.49,10.41 68.29,11.21 v2(68.29,11.24) ; 65.19,10.41 62.53,10.41 61.52,11.43 ; C116.2 v2(68.28,14.1) ; v2(65.75,14.34) 66.4,14.99 C117.2
  BOTTOM w0.508: C118.2 61.52,13.26 L3.2 61.52,10.26 C119.2
VCC5V0: length 59.1
  TOP w0.203: v3(12.33,56.83) 12.73,56.44 C139.1
  TOP w0.305: C135.1 8.31,54.84 v3(8.71,55.24) ; U17.10 v3(12.33,56.83) ; U17.11 v3(13.52,57.88)
  TOP w0.381: 10.43,14.85 U20.5 9.22,15.39 ; U16.10 23.94,57.54 ; 25.04,58.14 24.59,58.59 U16.11 24.47,58.18 ; 27.15,37.44 C146.1 26.34,36.63 ; 23.85,56.06 C138.1 24.66,56.92 ; 9.32,13.74 C152.1 10.13,12.85 ; U19.5 22.47,38.7 ; 21.77,56.62 22.12,56.97 U16.8 ; U19.11 27.17,38.8 ; U19.7 24.17,37.45 ; 19.77,57.85 U16.5 19.12,58.59 18.75,58.22 ; 26.59,37.62 26.12,38.09 U19.10 ; U16.7 21.47,56.73 ; 12.52,13.41 12.78,13.67 U20.8 ; U18.7 17.82,26.05 ; 15.32,27.76 15.62,28.06 U18.5 16.12,27.52
  TOP w0.508: U19.6 U19.7 U19.8 ; 14.5,14.07 14.24,14.34 U20.10 ; U17.5 7.65,57.79 v4(7.65,56.39) 8.09,56.83 U17.6 U17.7 U17.8 ; 15.11,46.35 L6.2 17.75,44.88 ; U18.10 20.33,27.01 ; U20.8 U20.7 U20.6 11.48,13.43 ; C150.1 17.55,47.57 ; U20.11 15.13,14.29 ; U18.11 20.82,27.34 ; U18.8 U18.7 U18.6 16.47,27.01 ; C156.1 14.35,12.6 ; U16.8 U16.7 U16.6 20.82,56.47
  TOP w0.61: 13.82,26.86 C147.1 ; C147.1 14.4,27.48 ; C147.1 13.82,28.11 ; 18.88,55.91 C134.1 ; C134.1 19.51,56.49 ; C134.1 20.13,55.91 ; 23.16,38.32 U19.6 23.52,37.61 ; C143.1 16.59,26.21 ; C143.1 17.21,25.63 ; C143.1 15.96,25.63 ; 18.41,48.2 C150.1 18.41,46.95 ; 21.36,39.19 C142.1 20.78,38.57 ; 13.35,44.88 L6.2 15.11,43.94
  TOP w1.016: C156.1 15.04,13.34
  BOTTOM w0.305: C151.1 v3(27.36,50.09)
  vias: v2(9.27,14.73) v2(10.13,14.07) v2(10.72,13.31) v2(10.87,12.45) v2(12.01,12.45) v2(12.65,44.17) v2(12.67,45.59) v2(13.08,49.15) v2(13.08,47.9) v2(13.08,46.86) v2(13.06,12.45) v2(13.94,25.93) v2(13.97,26.67) v2(14.68,26.67) v2(14.78,25.96) v2(15.27,49.15) v2(15.44,47.96) v2(15.6,46.94) v2(17.12,48.31) v2(17.35,49.23) v2(17.42,46.43) v2(18.31,45.29) v2(18.9,57.45) v2(18.87,56.67) v2(20.04,57.43) v2(20.73,25.63) v2(20.78,26.54) v2(21.06,55.75) v2(21.06,37.44) v2(21.08,36.6) v2(21.82,25.6) v2(21.89,26.54) v2(22.23,37.44) v2(22.23,36.63) v2(23.5,36.68) v2(24.05,56.92) v2(24.46,57.61) v2(25.04,57.61)
VCCADC: length 5.9
  TOP w0.152: v1(91.67,57.25) 91.15,56.74 U3.K10
  ART2 w0.152: v1(91.69,55.24) 91.69,55.27 92.1,55.68 92.1,56.82 v1(91.67,57.25)
  BOTTOM w0.152: v1(91.69,55.24) L2.1 92.56,55.6 C64.1 ; v1(91.67,57.25) 91.21,57.71 C63.1
0: length 1224
  TOP w0.152: J17.B24 112.52,93.4 v1(113.11,92.81) ; U3.D13 v1(97.62,53.25) ; v1(116.87,92.99) 116.33,93.52 J17.B27 ; U3.N8 v1(87.69,59.17) ; U3.F5 v1(95.62,62.17) ; U3.H21 v1(93.62,45.25) ; U3.C6 v1(98.62,61.17) ; U3.D3 v1(97.62,64.17) ; v1(91.64,58.19) 91.16,57.71 U3.K9 ; U3.Y15 v1(80.69,51.25) ; J17.B4 87.12,93.45 v1(87.71,92.86) ; J16.B25 50.04,93.47 v2(49.45,92.89) ; U3.Y5 v1(80.69,62.17) ; J17.B23 111.25,93.42 v1(111.84,92.84) ; U3.V21 v1(82.69,45.25) ; J16.B19 42.42,93.47 v2(41.83,92.89) ; v2(46.94,92.91) 47.5,93.47 J16.B23 ; U3.A9 v1(100.71,57.15) ; U3.B19 v1(99.62,47.25) ; J16.B27 52.58,93.52 v2(51.97,92.91) ; U3.C3 v1(98.62,64.17) ; v2(39.27,92.86) 39.88,93.47 J16.B17 ; v2(34.26,92.91) 34.8,93.45 J16.B13 ; J16.B15 37.34,93.55 v2(36.73,92.94) ; U3.K7 v1(91.62,60.17) ; v1(91.52,92.86) 90.93,93.45 J17.B7 ; U3.W18 v1(81.69,48.25) ; J17.B31 v1(121.41,92.99) ; J17.B33 v1(123.95,92.99) ; U3.L8 v1(90.62,59.17) ; v1(88.67,57.2) 89.15,56.72 U3.M10 ; v2(44.3,92.89) 44.96,93.55 J16.B21 ; J16.B37 65.28,93.6 v2(64.69,93.01) ; U3.V1 v1(83.15,66.24) ; J17.B29 v1(118.87,92.99) ; U3.M11 v1(88.69,56.17) ; v1(90.65,57.23) 90.15,56.73 U3.L10 ; U3.L9 90.2,57.71 v1(90.68,58.19) ; v1(87.6,58.27) 88.15,57.72 U3.N9 ; v1(89.64,60.17) 89.17,59.71 U3.M7 ; v1(99.11,92.86) 98.55,93.42 J17.B13 ; U3.L22 v1(90.15,44.07) ; v2(54.43,92.89) 55.12,93.57 J16.B29 ; U3.A7 v1(100.62,60.17) ; U3.H11 v1(93.62,56.17) ; U3.G6 v1(94.62,61.17) ; U3.E20 v1(96.62,46.25) ; U3.H7 v1(93.62,60.17) ; U3.G7 v1(94.62,60.17) ; U3.G9 94.08,57.71 v1(93.62,58.17) U3.H9 ; U3.M9 v1(88.7,58.17) ; J17.B21 108.71,93.52 v1(109.32,92.91) ; v1(101.73,92.89) 101.09,93.52 J17.B15 ; U3.U10 84.15,56.69 v1(83.67,56.21) ; J16.B35 62.74,93.4 v2(62.13,92.79) ; U3.J12 v1(92.62,54.25) ; v2(57.07,92.86) 57.66,93.45 J16.B31 ; U3.D12 v1(97.62,54.25) ; U3.W8 v1(81.69,59.17) ; U3.G12 v1(94.62,54.25) ; U3.P3 v1(86.69,64.17) ; U3.J10 v1(92.62,57.17) ; J17.B3 v1(86.61,92.91) ; U3.U14 v1(83.69,52.25) ; U3.P7 v1(86.69,60.17) ; U3.A11 v1(100.62,56.17) ; v1(87.63,57.23) 88.15,56.71 U3.N10 ; J16.B11 32.26,93.45 v2(31.65,92.84) ; J16.B39 67.82,93.6 v2(67.16,92.94) ; U3.L2 v1(90.62,65.17) ; U3.D8 v1(97.62,59.17) ; U3.T17 v1(84.69,49.25) ; U3.R12 v1(85.69,54.25) ; J17.B39 v1(131.57,92.96) ; J17.B28 v1(117.6,92.96) ; U3.A22 v1(100.62,44.25) ; v1(84.15,44.09) U3.U22 ; U3.A12 v1(100.62,54.25) ; U3.K11 v1(91.62,56.17) ; J17.B35 v1(126.49,92.99) ; J17.B11 96.01,93.42 v1(96.6,92.84) ; U3.AA22 v1(79.69,44.25) ; J17.B8 92.2,93.5 v1(92.79,92.91) ; U3.R20 v1(85.69,46.25) ; U3.G8 v1(94.62,59.17) ; U3.R10 v1(85.69,57.17) ; U3.B12 v1(99.62,54.25) ; U3.F17 v1(95.62,49.25) ; U3.H1 v1(93.15,66.24) ; U3.C16 v1(98.62,50.25) ; U3.G10 v1(94.62,57.17) ; U3.V11 v1(82.65,56.21) ; U3.C12 v1(98.62,54.25) ; J17.B19 106.17,93.4 v1(106.71,92.86) ; v1(104.17,92.86) 103.63,93.4 J17.B17 ; U3.D4 v1(97.62,63.17) ; U3.T11 v1(84.69,56.17) ; J16.B3 22.1,93.6 v2(21.46,92.96) ; U3.E7 v1(96.62,60.17) ; U3.M19 v1(88.69,47.25) ; U3.K5 v1(91.62,62.17) ; U3.B3 v1(99.62,64.17) ; v2(29.11,92.91) 29.72,93.52 J16.B9 ; U3.J18 v1(92.62,48.25) ; U4.2 v2(116.92,55.6) ; J16.B5 24.64,93.6 v2(24.05,93.01) ; R24.2 v2(108.81,57.15) ; U3.P11 v1(86.69,56.17) ; U3.K15 v1(91.62,51.25) ; U3.T7 v1(84.69,60.17) ; U3.R8 v1(85.69,59.17) ; U3.T9 v1(84.69,58.17) ; U3.N16 v1(87.69,50.25) ; U3.U4 v1(83.69,63.17) ; U3.C10 v1(98.62,57.17) ; U3.F11 v1(95.62,56.17) ; v2(26.54,92.94) 27.18,93.57 J16.B7 ; U3.E11 v1(96.62,56.17) ; U3.P13 v1(86.69,53.25) ; J16.B33 60.2,93.5 v2(59.56,92.86) ; U3.N6 v1(87.69,61.17) ; U3.AA2 v1(79.69,65.17) ; U3.E9 v1(96.62,58.17) ; U3.G14 v1(94.62,52.25) ; v1(96.65,54.23) 96.17,54.71 U3.E12 ; J17.B37 v1(129.03,92.94) ; U3.A5 v1(100.62,62.17) ; U3.G5 v1(94.62,62.17) ; U3.P9 v1(86.69,58.17) ; U3.A2 v1(100.62,65.17) ; U3.J8 v1(92.62,59.17) ; U3.A3 v1(100.62,64.17) ; U3.AB19 v1(78.51,47.71) ; U3.AB9 v1(78.59,57.71) ; U3.E4 v1(96.62,63.17) ; U3.E5 v1(96.62,62.17) ; U3.AA12 v1(79.69,54.25)
  TOP w0.203: 67.16,14.78 67.65,14.29 U12.13 67.65,10.68 68.07,10.26 ; C101.1 34.38,80.52 U6.2 ; v2(33.02,20.27) 33.3,20.55 U10.12 ; U12.17 70.19,14.54 69.85,14.88 ; U9.1 46.58,8 v2(46.46,8.13) ; U9.24 v2(46.48,5.26) ; U12.48 v2(65.11,23.94) ; 61.8,11.02 61.94,11.16 U12.4 ; DU1.11 v2(133.53,47.6) ; DU1.17 v2(128.73,44.35) ; U12.19 71.46,14.52 71.09,14.88 ; C139.2 v2(14.25,56.21) ; U12.7 63.84,11.8 64.26,11.38 ; DU1.10 v2(133.91,36.12) ; DU1.1 125.93,38.56 v2(125.93,38.73) ; v2(52.7,8.05) 52.58,7.93 U9.12 ; U9.13 v2(52.68,5.23) ; DU1.20 v2(126.31,47.42) ; DU1.14 v2(131.11,44.35)
  TOP w0.254: U8.1 29.89,7.93 28.93,8.89 ; 36.35,8.61 35.89,8.16 U8.12 ; U12.35 73.37,24.6 73.48,24.71 ; 74.42,24.61 74.64,24.4 U12.33
  TOP w0.305: R173.2 23.52,33.22 ; U17.12 12.99,58.53 v3(13.61,59.16) ; C149.2 24.79,30.66 ; U21.12 v3(10.37,76.92) ; U19.21 v3(24.59,40.67) ; R191.2 v3(10.62,83.54) ; U20.21 v3(12.75,16.69) ; U16.12 v3(25.8,59.24) ; C158.2 v2(1.24,75.69)
  TOP w0.381: J16.A14 36.07,95.66 ; 18.67,93.68 J16.B1 19.56,92.94 ; J16.A30 56.39,95.76 ; U18.12 22.16,28.71 ; J17.A25 113.79,95.73 ; J16.A38 66.55,95.78 ; J16.A40 69.09,95.86 ; J17.A12 97.28,95.73 ; J17.A22 109.98,95.71 ; J16.A8 28.45,95.68 ; 14.53,81.69 13.88,82.33 U7.1 ; J16.A32 58.93,95.71 ; U20.12 16.75,16.04 ; J16.A4 23.37,95.68 ; J16.A28 53.85,95.68 ; J16.A6 25.91,95.71 ; J16.A18 41.15,95.66 ; J16.A10 30.99,95.66 ; C104.2 14.96,90.22 ; J17.A18 104.9,95.66 ; J17.A30 120.14,95.66 ; J17.A36 127.76,95.73 ; J17.A16 102.36,95.81 ; J16.A24 48.77,95.78 ; J16.A2 20.83,95.63 ; J17.A28 117.6,95.78 ; J17.A14 99.82,95.76 ; C114.1 54.94,11.05 ; J16.A20 43.69,95.76 ; J17.A34 125.22,95.63 ; J16.A16 38.61,95.68 ; J16.A22 46.23,95.81 ; J17.A20 107.44,95.66 ; U19.12 28.59,40.02 ; J16.A36 64.01,95.78 ; J17.A38 130.3,95.71 ; J16.A12 33.53,95.71 ; U7.2 15.34,83.08 ; J16.A26 51.31,95.73 ; J16.A34 61.47,95.66 ; J17.A32 122.68,95.66 ; J17.A5 88.39,95.73
  TOP w0.508: D5.1 108.86,15.27 ; C135.2 6.15,55.75 ; C140.2 28.65,61.19 ; D3.1 113.03,15.24 ; C159.2 6.2,85.5 ; 6.2,85.5 6.2,88.67 ; 6.2,85.5 9.07,88.37 ; R7.2 111.3,9.55 ; U13.7 82.96,1.49 ; U8.13 35.99,5.18 36.47,4.7 ; C134.2 v4(20.78,54.38) ; C157.2 19.08,17.98 ; R172.2 30,44.86 ; C160.2 10.08,71.35 ; C146.2 28.04,35.1 ; U13.8 70.75,1.49 ; 16.97,60.48 C141.2 15.98,61.19 ; C164.1 36.6,28.22 ; D4.1 110.95,15.34 ; C138.2 26.19,57.05 ; C150.2 21.03,47.57 ; D20.1 14.17,7.32 ; U13.6 83,6.79 ; U8.24 29.79,5.31 29.24,4.75 ; U7.5 11.93,81.78 ; 31.78,36.86 D19.1 30.51,38.13 ; C58.2 99.09,23.04 ; U5.10 95.33,32.54 ; R183.2 17.81,20.95 ; C113.1 64.72,11 ; U13.9 70.63,6.79 ; U13.5 78.38,9.04
  TOP w0.61: 146.84,66.65 J4.3 ; J4.3 148.29,68.1 ; J4.3 148.29,65.2 ; J4.3 149.73,66.65 ; 41.59,22.96 U11.12 ; U11.12 44.02,22.54 ; U11.12 44.02,23.38 ; J2.3 147.12,83.16 ; J2.3 148.56,81.71 ; J2.3 145.67,81.71 ; J2.3 147.12,80.26 ; DU1.26 138.43,35.97 ; DU1.26 137.24,37.16 ; DU1.26 137.24,34.77 ; DU1.26 136.04,35.97 ; 140.59,76.63 J2.5 ; J2.5 142.04,75.18 ; J2.5 143.48,76.63 ; J2.5 142.04,78.08 ; 126.29,37.77 DU1.1 126.72,36.32 ; C152.2 9.94,11.33 ; C152.2 9.32,10.74 ; C152.2 8.7,11.33 ; 146.84,22.83 J1.3 ; J1.3 148.29,21.39 ; J1.3 148.29,24.28 ; J1.3 149.73,22.83 ; 25.92,16.74 U10.8 ; U10.8 28.35,17.16 ; U10.8 28.35,16.32 ; U10.8 30.77,16.74 ; C136.2 26.67,67.06 ; C136.2 25.48,68.38 ; C136.2 24.28,67.06 ; C136.2 25.48,65.74 ; 70.72,99.71 J16.4 ; J16.4 72.28,99.71 ; J16.4 71.5,98.18 ; D11.2 86.92,3.23 ; D11.2 86.11,2.54 ; D11.2 86.92,1.85 ; D11.2 87.73,2.54 ; 17.15,98.18 J16.2 ; J16.2 16.37,99.71 ; J16.2 17.93,99.71 ; 11.07,68.43 C137.2 ; C137.2 11.07,70.82 ; C137.2 9.75,69.62 ; C137.2 12.4,69.62 ; J5.2 149.73,40.36 ; J5.2 148.29,41.81 ; J5.2 146.84,40.36 ; J5.2 148.29,38.91 ; J7.3 44.6,60.52 ; J7.3 44.6,58.76 ; J7.3 45.48,59.64 ; J7.3 43.73,59.64 ; J17.3 136.03,94.31 ; J17.3 134.47,94.31 ; J17.3 135.25,95.84 ; J17.3 135.25,92.78 ; 84.58,95.52 J17.A2 84,94.95 ; 16.81,77.13 U6.15 15.57,77.13 ; 16.94,20.33 R183.2 16.94,21.58 ; U13.6 80.98,8.06 ; U13.6 80.98,5.52 ; U13.6 79.56,6.79 ; J6.5 144.65,51.13 ; J6.5 141.76,51.13 ; J6.5 143.21,52.58 ; J6.5 143.21,49.68 ; J5.3 149.73,45.44 ; J5.3 148.29,43.99 ; J5.3 148.29,46.89 ; J5.3 146.84,45.44 ; 133.42,94.95 J17.A40 132.84,95.52 ; 81.25,19.1 U15.1 ; U15.1 83.9,19.1 ; U15.1 82.58,20.42 ; U15.1 82.58,17.78 ; 48.78,26.77 U11.8 ; U11.8 51.21,27.19 ; U11.8 51.21,26.35 ; U11.8 53.63,26.77 ; J1.4 143.21,24.28 ; J1.4 144.65,22.83 ; J1.4 141.76,22.83 ; J1.4 143.21,21.39 ; 121.79,11.48 DU1.39 ; DU1.39 122.99,12.67 ; DU1.39 124.18,11.48 ; DU1.39 122.99,10.29 ; J7.11 44.6,50.36 ; J7.11 43.73,49.48 ; J7.11 44.6,48.6 ; J7.11 45.48,49.48 ; 18.67,39.19 C142.2 ; C142.2 19.25,38.57 ; C142.2 19.25,39.81 ; 33.78,63.63 D18.1 ; D18.1 32.97,64.31 ; D18.1 34.59,64.31 ; D18.1 33.78,65 ; C58.2 100.1,21.79 ; C58.2 99.09,20.68 ; C58.2 98.09,21.79 ; 26.53,35.1 C146.2 27.15,34.52 ; D8.1 103.43,16.18 ; D8.1 101.8,16.18 ; D8.1 102.62,15.49 ; D8.1 102.62,16.87 ; C148.2 30.25,42.58 ; C148.2 30.25,41.34 ; C148.2 30.84,41.96 ; 133.97,96.95 J17.6 ; J17.6 135.05,95.87 ; J17.6 135.05,98.02 ; J17.6 136.13,96.95 ; 148.29,54.76 J6.3 ; J6.3 149.73,56.21 ; J6.3 148.29,57.66 ; J6.3 146.84,56.21 ; 108.05,16.18 D5.1 ; D5.1 109.68,16.18 ; D5.1 108.86,16.87 ; 80.9,92.78 J17.1 ; J17.1 80.12,94.31 ; J17.1 80.9,95.84 ; J17.1 81.68,94.31 ; 80.12,99.71 J17.2 ; J17.2 80.9,98.18 ; J17.2 81.68,99.71 ; DU1.37 122.99,32.16 ; DU1.37 124.18,30.96 ; DU1.37 122.99,29.77 ; DU1.37 121.79,30.96 ; 16.37,94.31 J16.1 ; J16.1 17.93,94.31 ; J16.1 17.15,92.78 ; J16.1 17.15,95.84 ; J1.5 144.65,17.75 ; J1.5 143.21,16.31 ; J1.5 141.76,17.75 ; J1.5 143.21,19.2 ; 148.29,16.31 J1.2 ; J1.2 149.73,17.75 ; J1.2 148.29,19.2 ; J1.2 146.84,17.75 ; 90.68,11.46 U14.3 ; U14.3 91.49,10.64 ; U14.3 92.3,11.46 ; U14.3 91.49,12.27 ; J5.5 144.65,40.36 ; J5.5 141.76,40.36 ; J5.5 143.21,38.91 ; J5.5 143.21,41.81 ; J3.5 144.65,29.24 ; J3.5 143.21,30.68 ; J3.5 141.76,29.24 ; J3.5 143.21,27.79 ; J17.5 81.1,98.02 ; J17.5 80.02,96.95 ; J17.5 82.18,96.95 ; J17.5 81.1,95.87 ; J12.1 5.08,9.32 ; J12.1 5.08,0.84 ; J12.1 9.32,5.08 ; 134.06,29.77 DU1.41 ; DU1.41 134.06,32.16 ; DU1.41 132.87,30.96 ; DU1.41 135.26,30.96 ; 122.99,21.46 122.99,22.66 ; 122.99,21.46 122.99,20.27 ; 122.99,21.46 121.79,21.46 ; 122.99,21.46 124.18,21.46 ; 148.29,60.12 J4.2 ; J4.2 149.73,61.57 ; J4.2 146.84,61.57 ; J4.2 148.29,63.02 ; 54.2,61.57 J8.1 ; J8.1 53.26,62.51 ; J8.1 55.14,62.51 ; J8.1 54.2,63.45 ; 71.5,92.78 J16.3 ; J16.3 70.72,94.31 ; J16.3 72.28,94.31 ; J16.3 71.5,95.84 ; 82.73,94.95 J17.A1 ; J17.A1 83.89,94.95 ; J17.A1 83.31,95.52 ; D4.1 110.95,16.87 ; D4.1 111.76,16.18 ; D4.1 110.13,16.18 ; J15.1 94.49,14.88 ; J15.1 94.49,13 ; J15.1 93.55,13.94 ; J15.1 95.43,13.94 ; 148.29,32.87 J3.3 ; J3.3 146.84,34.32 ; J3.3 149.73,34.32 ; J3.3 148.29,35.76 ; 94.05,94.95 J17.A9 93.47,95.52 ; DU1.40 132.77,11.38 ; DU1.40 131.57,12.57 ; DU1.40 131.57,10.19 ; DU1.40 130.38,11.38 ; 43.73,54.56 J7.7 ; J7.7 45.48,54.56 ; J7.7 44.6,53.68 ; J7.7 44.6,55.44 ; 116.38,16.18 D1.1 ; D1.1 117.2,16.87 ; D1.1 118.01,16.18 ; D1.1 117.2,15.49 ; J7.13 45.48,46.94 ; J7.13 44.6,46.06 ; J7.13 44.6,47.82 ; J7.13 43.73,46.94 ; J6.2 148.29,52.58 ; J6.2 148.29,49.68 ; J6.2 149.73,51.13 ; J6.2 146.84,51.13 ; J5.4 144.65,45.44 ; J5.4 143.21,46.89 ; J5.4 143.21,43.99 ; J5.4 141.76,45.44 ; 3.12,34.06 J18.4 ; J18.4 6.27,34.06 ; J18.4 4.7,32.49 ; C156.2 17.15,12.6 ; C156.2 16.56,11.98 ; C156.2 16.56,13.22 ; 26.7,63.49 R165.2 ; R165.2 26.7,64.73 ; R165.2 27.28,64.11 ; 11.16,82.43 U7.5 11.93,82.79 ; 94.74,95.52 J17.A10 94.16,94.95 ; D21.1 16.92,52.35 ; D21.1 16.1,51.66 ; D21.1 16.1,53.04 ; D21.1 15.29,52.35 ; 143.21,65.2 J4.4 ; J4.4 143.21,68.1 ; J4.4 141.76,66.65 ; J4.4 144.65,66.65 ; 83.87,13.18 U14.7 ; U14.7 83.87,14.81 ; U14.7 83.06,14 ; U14.7 84.68,14 ; 72.58,2.76 U13.8 74.01,1.49 ; 14.88,6.5 D20.1 ; D20.1 15.57,7.32 ; D20.1 14.88,8.13 ; J7.9 45.48,52.02 ; J7.9 44.6,51.14 ; J7.9 44.6,52.9 ; J7.9 43.73,52.02 ; D16.2 9.83,49.89 ; D16.2 8.46,49.89 ; D16.2 9.14,50.7 ; D16.2 9.14,49.07 ; 141.76,34.32 J3.4 ; J3.4 143.21,35.76 ; J3.4 144.65,34.32 ; 8.33,30 C145.2 ; C145.2 10.72,30 ; C145.2 9.53,31.32 ; C145.2 9.53,28.68 ; J16.6 71.3,98.02 ; J16.6 70.22,96.95 ; J16.6 72.38,96.95 ; J16.6 71.3,95.87 ; 125.88,45.97 DU1.20 126.31,44.53 ; DU1.29 137.24,47.17 ; DU1.29 138.43,45.97 ; DU1.29 136.04,45.97 ; DU1.29 137.24,44.78 ; 134.47,99.71 J17.4 ; J17.4 136.03,99.71 ; J17.4 135.25,98.18 ; D3.1 113.84,16.18 ; D3.1 112.22,16.18 ; D3.1 113.03,16.87 ; 44.6,61.3 J7.1 ; J7.1 43.73,62.18 ; J7.1 45.48,62.18 ; J7.1 44.6,63.06 ; 114.3,16.18 D2.1 ; D2.1 115.93,16.18 ; D2.1 115.11,15.49 ; D2.1 115.11,16.87 ; 15.96,24.1 C143.2 ; C143.2 16.59,23.52 ; C143.2 17.21,24.1 ; 91.49,13.18 U14.2 ; U14.2 90.68,14 ; U14.2 91.49,14.81 ; U14.2 92.3,14 ; 106.78,15.49 D6.1 ; D6.1 106.78,16.87 ; D6.1 105.97,16.18 ; D6.1 107.59,16.18 ; 18.19,18.61 C157.2 18.19,17.36 ; 147.32,92.28 J9.1 143.08,96.52 ; 92.3,21.07 C57.2 ; C57.2 92.89,21.69 ; C57.2 92.3,22.31 ; 18.88,54.38 C134.2 19.51,53.8 ; 27.81,60.57 C140.2 27.81,61.81 ; 5.08,92.28 J11.1 9.32,96.52 ; 147.32,0.84 J10.1 ; J10.1 143.08,5.08 ; J10.1 147.32,9.32 ; J16.5 18.43,96.95 ; J16.5 16.27,96.95 ; J16.5 17.35,98.02 ; J16.5 17.35,95.87 ; 72.58,5.52 U13.9 ; U13.9 72.58,8.06 ; U13.9 74.01,6.79 ; 11.71,27.48 C147.2 ; C147.2 12.29,28.11 ; C147.2 12.29,26.86 ; 23.95,31.28 C149.2 23.95,30.04 ; 5.56,54.84 C135.2 6.15,54.22 ; 104.7,15.49 D7.1 ; D7.1 103.89,16.18 ; D7.1 104.7,16.87 ; D7.1 105.51,16.18 ; 8.42,71.35 C160.2 9.04,70.76 ; DU1.42 128.68,32.16 ; DU1.42 128.68,29.77 ; DU1.42 129.87,30.96 ; DU1.42 127.48,30.96 ; 110.41,8.93 R7.2 110.41,10.17 ; 133.91,39.22 DU1.10 134.34,37.77 ; 65.3,10.39 C113.1 64.72,9.77 ; J3.2 148.29,30.68 ; J3.2 148.29,27.79 ; J3.2 149.73,29.24 ; J3.2 146.84,29.24 ; 16.78,90.22 C104.2 16.15,90.81 ; U14.4 92.3,8.92 ; U14.4 91.49,8.1 ; U14.4 90.68,8.92 ; U14.4 91.49,9.73 ; J7.5 45.48,57.1 ; J7.5 44.6,56.22 ; J7.5 44.6,57.98 ; J7.5 43.73,57.1 ; 29.16,44.23 R172.2 29.16,45.48 ; 26.19,55.44 C138.2 26.77,56.06 ; 54.36,10.06 C114.1 54.94,9.44 ; 141.76,61.57 J4.5 ; J4.5 143.21,63.02 ; J4.5 143.21,60.12 ; J4.5 144.65,61.57 ; DU1.24 137.24,27.66 ; DU1.24 137.24,25.27 ; DU1.24 136.04,26.47 ; DU1.24 138.43,26.47 ; 137.24,15.27 DU1.23 ; DU1.23 136.04,16.46 ; DU1.23 138.43,16.46 ; DU1.23 137.24,17.65 ; 5.49,15.01 C153.2 6.81,13.82 ; 141.76,56.21 J6.4 ; J6.4 143.21,57.66 ; J6.4 144.65,56.21 ; J6.4 143.21,54.76 ; J2.4 143.48,81.71 ; J2.4 142.04,83.16 ; J2.4 142.04,80.26 ; J2.4 140.59,81.71 ; 22.63,33.85 R173.2 22.63,32.6 ; 79.56,1.49 U13.7 80.98,2.76 ; R166.2 14.76,63.97 ; R166.2 14.76,62.73 ; R166.2 15.34,63.35 ; 27.89,30.02 D17.1 ; D17.1 27.2,30.84 ; D17.1 28.58,30.84 ; J2.2 148.56,76.63 ; J2.2 147.12,78.08 ; J2.2 145.67,76.63 ; J2.2 147.12,75.18 ; 14.83,55.17 C139.2 14.25,54.55 ; 133.53,44.53 DU1.11 133.96,45.97 ; 89.08,94.95 J17.A6 89.66,95.52
  BOTTOM w0.152: 92.33,57.63 92.33,57.46 v1(92.62,57.17) ; v1(99.57,59.23) 100.1,58.7 C48.2 ; C68.2 93.04,59.6 v1(92.62,59.17) ; C75.2 90.35,58.91 v1(90.62,59.17) 90.53,59.27 C69.2 ; v1(79.69,54.25) 79.73,54.2 C90.2 ; C40.2 94.82,58.97 v1(94.62,59.17) ; v1(93.62,60.17) 94.08,60.64 C38.2 ; C24.2 90.12,63.73 90.12,64.14 90.62,64.64 v1(90.62,65.17) ; C44.2 99.09,56.71 v1(98.62,57.17) ; v1(97.62,63.17) 98.09,62.7 C42.2 ; v1(91.62,51.25) 91.44,51.07 C10.2 ; v1(86.61,47.19) 87.07,46.74 C97.2 ; C89.2 79.07,57.23 v1(78.59,57.71) ; C64.2 v1(94.64,56.18) ; v1(99.62,47.25) 99.44,47.07 C19.2 ; C87.2 89.03,56.85 v1(88.67,57.2) ; v1(95.62,49.25) 96.01,48.85 C18.2 ; v1(95.62,56.17) 95.91,56.47 C76.2 ; C65.2 98.22,61.57 v1(98.62,61.17) ; C60.2 85.09,53.64 v1(85.69,54.25) ; v1(96.62,58.17) 96.9,57.89 C67.2 ; v1(84.69,49.25) 84.24,48.79 C99.2 ; C92.2 81.06,50.88 v1(80.69,51.25) ; v1(86.69,60.17) 87.2,59.66 87.25,59.66 ; C33.2 v1(77.39,60.15) ; C25.2 87.43,61.44 v1(87.69,61.17) ; C13.2 89.87,46.84 v1(89.64,47.07) ; v1(82.65,56.21) 82.91,56.46 C88.2 ; C63.2 90.2,57.71 v1(90.68,58.19) ; v1(80.69,51.25) 81.56,52.12 C94.2 ; v1(80.69,51.25) 80.34,50.9 C93.2 ; v1(93.62,45.25) 94.13,44.73 C20.2 ; v1(91.62,56.17) 91.14,56.66 C78.2 ; C9.2 94.16,53.79 v1(94.62,54.25) 94.64,54.27 C81.2 ; C86.2 82.06,58.8 v1(81.69,59.17) 82.23,59.72 C61.2 ; C26.2 91.82,61.97 v1(91.62,62.17) ; C23.2 86.54,66.55 v1(86.11,66.98) ; R33.2 v2(150.85,53.64) ; C37.2 102.95,57.25 v2(102.87,57.18) ; C34.2 81.61,65.91 81.99,66.29 v1(81.99,67.31) ; C77.2 91.16,60.63 v1(91.62,60.17) ; C16.2 96.14,50.62 v1(95.71,50.19) ; C49.2 104.93,65.35 v2(105.44,65.86) ; v1(76.12,62.69) 76.25,62.56 C29.2 ; C11.2 89.94,47.9 v1(89.64,48.21) ; C36.2 100.57,60.22 v1(100.62,60.17) ; v1(84.15,44.09) 84.3,44.24 C98.2 ; C46.2 100.43,61.99 v1(100.62,62.17) ; v1(84.69,60.17) 84.56,60.04 C71.2 ; v1(88.69,56.17) 88.7,56.17 C74.2 ; C39.2 v1(103.68,54.46) ; v1(92.62,48.25) 92.98,47.88 C12.2 ; C85.2 85.9,58.96 v1(85.69,59.17) ; v1(84.66,67.64) 84.89,67.41 C30.2 ; v1(83.69,52.25) 83.79,52.14 C96.2 ; C91.2 v1(76.81,52.48) ; C66.2 97.33,59.46 v1(97.62,59.17) ; C95.2 90.14,51.74 v1(89.69,52.2) 89.38,52.5 C83.2 ; C17.2 98.27,49.9 v1(98.62,50.25) ; v1(100.62,65.17) 100,65.79 C27.2 ; v1(84.66,61.24) 84.3,60.88 C32.2 ; v1(97.62,53.25) 98.16,52.7 C15.2 ; C28.2 86.54,64.32 v1(86.69,64.17) ; R47.1 v2(111.91,54.43) ; R23.2 v2(149.38,79.17) ; R20.2 v2(150.67,20.24) ; R29.2 v2(150.93,64.11) ; v1(86.69,52.12) 87,52.43 C80.2 ; C59.2 96.8,54.38 v1(96.65,54.23) ; v1(84.63,62.2) 85.04,61.8 C31.2 ; C79.2 84.12,56.67 v1(83.67,56.21) ; C47.2 v2(105.31,66.9) ; C72.2 85.18,57.68 v1(84.69,58.17) ; C84.2 87.66,54.74 86.69,55.7 v1(86.69,56.17) ; C82.2 v1(90.6,53.16) ; v1(85.69,46.25) 86.21,45.72 C14.2
  BOTTOM w0.203: v2(64.08,26.97) 63.63,26.52 C108.1 ; DR8.2 v2(134.65,37.62) ; C41.2 100.97,59.82 v1(100.62,60.17) ; DR15.2 v2(139.14,41.78) ; DR16.2 v2(128.98,39.57) ; C2.1 v2(92.84,37.59) ; R27.2 v2(150.98,32.64) ; v2(114.43,54.2) 114.25,54.03 C21.2 ; DR13.2 v2(138.4,32.36) ; C118.1 v2(58.14,14.12) ; R31.2 v2(151,42.88) ; C22.2 v2(114.17,56.79)
  BOTTOM w0.305: C128.2 125.53,44.02
  BOTTOM w0.508: U1.2 87.93,29.34 ; C129.2 133.73,48.49 134.26,49.02 ; 87.88,39.09 88.47,38.51 C3.1 ; C116.1 69.11,16.48 ; C122.2 134.42,50.37 ; C155.2 2.87,73.58 ; C125.2 132.38,53.98 ; C112.1 74.17,10.87 ; C165.1 26.72,21.82 ; C4.1 93.7,29.59 ; R6.1 107.62,30.76 ; C121.2 123.75,52.73 ; C7.2 101.47,33.27 ; U2.3 101.27,29.31 ; C117.1 66.6,17.22 ; 59.13,8.53 C119.1 57.63,9.4 ; R178.2 10.49,45.95 ; C161.2 10.31,80.34 ; R53.1 72.75,18.03 ; C154.2 1.78,62.99 ; C151.2 22.15,52.37
  BOTTOM w0.61: 123.56,46.38 DR7.2 ; DR7.2 124.8,46.38 ; DR7.2 124.18,46.96 ; 143.21,54.76 J6.4 ; J6.4 143.21,57.66 ; J6.4 144.65,56.21 ; 148.29,16.31 J1.2 ; J1.2 146.84,17.75 ; J1.2 149.73,17.75 ; J1.2 148.29,19.2 ; J5.2 149.73,40.36 ; J5.2 148.29,38.91 ; J5.2 148.29,41.81 ; J5.2 146.84,40.36 ; 147.12,80.26 J2.3 ; J2.3 147.12,83.16 ; J2.3 148.56,81.71 ; J2.3 145.67,81.71 ; J1.4 143.21,24.28 ; J1.4 143.21,21.39 ; J1.4 141.76,22.83 ; J1.4 144.65,22.83 ; 80.02,96.95 J17.5 ; J17.5 81.1,95.87 ; J17.5 81.1,98.02 ; J17.5 82.18,96.95 ; C115.2 91.89,24.38 ; C115.2 90.89,25.5 ; C115.2 89.88,24.38 ; C115.2 90.89,23.27 ; 121.79,30.96 DU1.37 ; DU1.37 122.99,29.77 ; DU1.37 124.18,30.96 ; DU1.37 122.99,32.16 ; 133.98,45.97 C130.2 ; C130.2 134.98,44.86 ; C130.2 135.99,45.97 ; C130.2 134.98,47.09 ; 141.76,66.65 J4.4 ; J4.4 143.21,65.2 ; J4.4 144.65,66.65 ; J4.4 143.21,68.1 ; J7.5 44.6,57.98 ; J7.5 45.48,57.1 ; J7.5 44.6,56.22 ; J7.5 43.73,57.1 ; 73.33,11.49 C112.1 73.33,10.25 ; J11.1 5.08,100.76 ; J11.1 9.32,96.52 ; J11.1 5.08,92.28 ; J11.1 0.84,96.52 ; 44.6,51.14 J7.9 ; J7.9 45.48,52.02 ; J7.9 44.6,52.9 ; J7.9 43.73,52.02 ; 121.93,50.5 C123.2 ; C123.2 122.93,51.61 ; C123.2 122.93,49.38 ; C123.2 123.93,50.5 ; 139.57,59.75 C124.2 ; C124.2 140.69,60.75 ; C124.2 141.81,59.75 ; C124.2 140.69,58.74 ; J4.3 149.73,66.65 ; J4.3 146.84,66.65 ; J4.3 148.29,68.1 ; J4.3 148.29,65.2 ; J2.5 143.48,76.63 ; J2.5 142.04,78.08 ; J2.5 140.59,76.63 ; J2.5 142.04,75.18 ; J3.3 149.73,34.32 ; J3.3 146.84,34.32 ; J3.3 148.29,35.76 ; J3.3 148.29,32.87 ; J7.7 44.6,55.44 ; J7.7 44.6,53.68 ; J7.7 45.48,54.56 ; J7.7 43.73,54.56 ; 101.47,31.71 C7.2 100.89,32.33 ; C132.2 134.32,57.63 ; C132.2 134.32,55.4 ; C132.2 133.32,56.52 ; C132.2 135.32,56.52 ; 121.79,11.48 DU1.39 ; DU1.39 122.99,12.67 ; DU1.39 124.18,11.48 ; DU1.39 122.99,10.29 ; 2.84,63.58 C154.2 3.47,62.99 ; 135.05,95.87 J17.6 ; J17.6 135.05,98.02 ; J17.6 133.97,96.95 ; J17.6 136.13,96.95 ; 148.46,79.79 R23.2 148.46,78.55 ; O1.3 120.47,61.58 ; O1.3 120.47,59.63 ; O1.3 121.4,60.6 ; O1.3 119.55,60.6 ; 43.73,46.94 J7.13 ; J7.13 44.6,46.06 ; J7.13 45.48,46.94 ; J7.13 44.6,47.82 ; 149.91,63.49 R29.2 149.91,64.73 ; 122.99,42.16 DU1.34 121.79,40.97 ; 96.99,30.25 C8.2 ; C8.2 97.61,30.84 ; C8.2 98.23,30.25 ; DU1.26 138.43,35.97 ; DU1.26 136.04,35.97 ; DU1.26 137.24,34.77 ; DU1.26 137.24,37.16 ; 146.84,56.21 J6.3 ; J6.3 148.29,54.76 ; J6.3 148.29,57.66 ; J6.3 149.73,56.21 ; U14.2 91.49,14.81 ; U14.2 90.68,14 ; U14.2 91.49,13.18 ; U14.2 92.3,14 ; 133.55,51.24 C131.2 133.55,52.49 ; J5.5 144.65,40.36 ; J5.5 143.21,38.91 ; J5.5 143.21,41.81 ; 141.76,17.75 J1.5 ; J1.5 143.21,16.31 ; J1.5 143.21,19.2 ; J1.5 144.65,17.75 ; 131.57,10.19 DU1.40 ; DU1.40 130.38,11.38 ; DU1.40 132.77,11.38 ; DU1.40 131.57,12.57 ; 44.6,48.6 J7.11 ; J7.11 45.48,49.48 ; J7.11 44.6,50.36 ; J7.11 43.73,49.48 ; 27.64,21.2 C165.1 27.64,22.44 ; 11.23,80.92 C161.2 11.85,80.34 ; J15.1 94.49,14.88 ; J15.1 94.49,13 ; J15.1 93.55,13.94 ; J15.1 95.43,13.94 ; C106.1 64.06,8 ; C106.1 63.47,7.38 ; C106.1 63.47,8.62 ; 149.96,53.02 R33.2 149.96,54.27 ; DU1.41 134.06,32.16 ; DU1.41 135.26,30.96 ; DU1.41 134.06,29.77 ; DU1.41 132.87,30.96 ; DU1.42 129.87,30.96 ; DU1.42 128.68,32.16 ; DU1.42 128.68,29.77 ; DU1.42 127.48,30.96 ; 0.84,5.08 J12.1 ; J12.1 9.32,5.08 ; J12.1 5.08,9.32 ; J12.1 5.08,0.84 ; C144.2 29.03,47.6 ; C144.2 27.84,46.28 ; C144.2 26.64,47.6 ; C144.2 27.84,48.92 ; J2.4 143.48,81.71 ; J2.4 142.04,80.26 ; J2.4 142.04,83.16 ; J2.4 140.59,81.71 ; 81.25,19.1 U15.1 ; U15.1 82.58,20.42 ; U15.1 83.9,19.1 ; U15.1 82.58,17.78 ; 146.84,29.24 J3.2 ; J3.2 149.73,29.24 ; J3.2 148.29,27.79 ; J3.2 148.29,30.68 ; J7.3 45.48,59.64 ; J7.3 44.6,58.76 ; J7.3 43.73,59.64 ; J7.3 44.6,60.52 ; 90.68,11.46 U14.3 ; U14.3 91.49,12.27 ; U14.3 92.3,11.46 ; U14.3 91.49,10.64 ; DU1.24 138.43,26.47 ; DU1.24 136.04,26.47 ; DU1.24 137.24,25.27 ; DU1.24 137.24,27.66 ; J6.2 148.29,52.58 ; J6.2 146.84,51.13 ; J6.2 149.73,51.13 ; J6.2 148.29,49.68 ; 115.24,33.78 SW2.1 ; SW2.1 113.92,35.1 ; SW2.1 115.24,36.42 ; SW2.1 116.56,35.1 ; 143.21,49.68 J6.5 ; J6.5 141.76,51.13 ; J6.5 144.65,51.13 ; J6.5 143.21,52.58 ; 121.79,21.46 122.99,21.46 ; 122.99,21.46 124.18,21.46 ; 122.99,21.46 122.99,22.66 ; 122.99,21.46 122.99,20.27 ; J9.1 147.32,100.76 ; J9.1 143.08,96.52 ; J9.1 147.32,92.28 ; J5.4 143.21,46.89 ; J5.4 141.76,45.44 ; J5.4 143.21,43.99 ; J5.4 144.65,45.44 ; 64.25,26.04 C108.1 63,26.04 ; 124.69,52.11 C121.2 124.69,53.35 ; 143.08,5.08 J10.1 ; J10.1 147.32,0.84 ; J10.1 147.32,9.32 ; C107.1 68.22,9.23 ; C107.1 68.22,7.99 ; C107.1 68.81,8.61 ; J2.2 147.12,78.08 ; J2.2 147.12,75.18 ; J2.2 145.67,76.63 ; J2.2 148.56,76.63 ; U14.7 83.87,14.81 ; U14.7 83.87,13.18 ; U14.7 84.68,14 ; U14.7 83.06,14 ; 4.7,32.49 J18.4 ; J18.4 3.12,34.06 ; J18.4 6.27,34.06 ; J18.4 4.7,35.64 ; J3.5 144.65,29.24 ; J3.5 143.21,30.68 ; J3.5 141.76,29.24 ; J3.5 143.21,27.79 ; J3.4 143.21,35.76 ; J3.4 141.76,34.32 ; J3.4 144.65,34.32 ; J3.4 143.21,32.87 ; C6.2 116,68.77 ; C6.2 116,67.53 ; C6.2 115.42,68.15 ; J4.2 149.73,61.57 ; J4.2 148.29,60.12 ; J4.2 146.84,61.57 ; J4.2 148.29,63.02 ; 74,16.71 C111.1 ; C111.1 74.63,17.3 ; C111.1 75.25,16.71 ; C102.2 31,78.44 ; C102.2 29.15,78.44 ; C102.2 30.07,79.36 ; C102.2 30.07,77.51 ; 16.81,77.13 U6.15 15.57,77.13 ; 32.07,78.4 U6.5 33.31,78.4 ; 135.27,38.53 DR8.2 134.02,38.53 ; 32.07,82.21 U6.2 33.31,82.21 ; 32.07,74.59 U6.8 33.31,74.59 ; C151.2 24.05,53.7 ; C151.2 25.25,52.37 ; C151.2 24.05,51.05 ; 9.5,46.57 R178.2 9.5,45.33 ; 148.29,21.39 J1.3 ; J1.3 146.84,22.83 ; J1.3 149.73,22.83 ; J1.3 148.29,24.28 ; C110.1 76.57,18.59 ; C110.1 75.95,18.01 ; C110.1 75.32,18.59 ; 4.19,71.91 C155.2 1.55,71.91 ; 125.58,43.38 C128.2 126.16,44.01 ; 70.22,19 C109.1 ; C109.1 70.84,18.41 ; C109.1 71.46,19 ; 18.43,96.95 J16.5 17.35,95.87 ; 73.37,17.17 R53.1 72.12,17.17 ; U1.2 86.39,30.54 ; U1.2 85.32,29.34 ; U1.2 86.39,28.15 ; 91.49,8.1 U14.4 ; U14.4 91.49,9.73 ; U14.4 92.3,8.92 ; U14.4 90.68,8.92 ; 136.04,16.46 DU1.23 ; DU1.23 137.24,15.27 ; DU1.23 138.43,16.46 ; DU1.23 137.24,17.65 ; J7.1 45.48,62.18 ; J7.1 44.6,61.3 ; J7.1 44.6,63.06 ; J7.1 43.73,62.18 ; 54.2,61.57 J8.1 ; J8.1 53.26,62.51 ; J8.1 54.2,63.45 ; J8.1 55.14,62.51 ; 143.21,60.12 J4.5 ; J4.5 143.21,63.02 ; J4.5 141.76,61.57 ; J4.5 144.65,61.57 ; J16.6 71.3,98.02 ; J16.6 72.38,96.95 ; J16.6 71.3,95.87 ; J16.6 70.22,96.95 ; DU1.29 138.43,45.97 ; DU1.29 137.24,47.17 ; DU1.29 136.04,45.97 ; DU1.29 137.24,44.78 ; 150.34,43.5 R31.2 150.34,42.25 ; 133.45,47.87 C129.2 133.45,49.11 ; 149.91,19.62 R20.2 149.91,20.87 ; 56.24,20.61 C167.1 ; C167.1 56.24,21.86 ; C167.1 56.82,21.23 ; J5.3 148.29,46.89 ; J5.3 146.84,45.44 ; J5.3 148.29,43.99 ; J5.3 149.73,45.44 ; 12.48,79.17 C105.2 ; C105.2 13.11,78.59 ; C105.2 13.73,79.17 ; 67.65,16.48 C116.1 68.28,17.07 ; 128.98,37.55 DR16.2 129.57,38.18 ; 40.89,18.14 C166.1 41.48,18.76 ; 133.55,50.99 C122.2 133.55,49.75
  vias: v2(1.07,63.65) v2(4.06,15.72) v2(4.14,14.83) v2(4.17,13.69) v2(4.22,12.57) v2(4.34,63.7) v2(5.31,56.77) v2(5.28,53.14) v2(5.66,12.73) v2(6.02,78.36) v2(5.97,76.53) v2(6.17,56.77) v2(6.22,53.21) v2(6.43,27.43) v2(6.48,29.97) v2(6.86,32.69) v2(6.86,12.65) v2(7.01,77.57) v2(7.01,77.57) v2(7.01,77.57) v2(6.99,72.64) v2(7.04,69.24) v2(7.26,11.33) v2(7.34,9.65) v2(8.41,47.27) v2(8.66,69.32) v2(8.81,59.03) v2(8.84,58.14) v2(8.84,44.58) v2(8.99,60.5) v2(9.32,9.63) v2(9.5,32.69) v2(9.58,57.96) v2(9.58,27.46) v2(9.86,60.48) v2(10.03,44.53) v2(10.44,46.94) v2(11.02,9.58) v2(11.1,11.2) v2(11.23,46.94) v2(11.25,46.23) v2(11.28,44.86) v2(11.3,7.57) v2(11.46,72.64) v2(11.48,2.92) v2(11.84,17.75) v2(11.76,15.42) v2(12.8,17.91) v2(12.75,7.29) v2(12.8,5.13) v2(12.93,15.39) v2(13.49,17.93) v2(13.97,72.69) v2(14.12,77.27) v2(14.15,76.28) v2(14.15,69.6) v2(14.2,100.1) v2(14.27,66.22) v2(14.33,65) v2(14.33,61.95) v2(14.27,24.1) v2(14.27,22.33) v2(14.96,5.13) v2(15.24,66.22) v2(15.16,61.95) v2(15.27,65.02) v2(15.44,94.18) v2(16.61,61.39) v2(16.59,19.56) v2(16.56,14.4) v2(16.56,10.97) v2(16.87,22.61) v2(17.37,91.72) v2(17.45,28.27) v2(17.42,5.13) v2(17.53,30.23) v2(17.58,61.06) v2(17.55,60.3) v2(17.55,59.59) v2(18.14,76.12) v2(18.11,19.56) v2(18.34,77.22) v2(18.29,16.08) v2(18.36,14.4) v2(18.36,12.65) v2(18.47,29.36) v2(18.47,29.36) v2(18.47,29.36) v2(18.47,29.36) v2(18.47,29.36) v2(18.47,29.36) v2(18.47,29.36) v2(18.47,29.36) v2(18.47,29.36) v2(18.57,11) v2(18.95,28.19) v2(19.13,42.29) v2(19.1,41.05) v2(19.2,37.72) v2(19.23,36.5) v2(19.81,23.7) v2(19.99,100) v2(20.07,22.63) v2(20.07,20.93) v2(20.14,17.83) v2(20.45,42.29) v2(20.5,41.1) v2(20.9,59.89) v2(21.06,98.6) v2(21.06,96.85) v2(21.21,19.58) v2(21.18,17.83) v2(21.18,7.37) v2(21.18,3.43) v2(21.36,60.83) v2(21.39,58.93) v2(21.54,12.12) v2(21.67,48.74) v2(21.67,46.84) v2(22.15,59.84) v2(22.71,98.68) v2(22.71,96.93) v2(23.14,22.12) v2(23.06,21.03) v2(24.43,7.49) v2(24.56,98.68) v2(24.56,96.93) v2(24.66,3.17) v2(25.63,22.28) v2(25.6,21.26) v2(26.11,30.94) v2(26.16,29.08) v2(26.52,98.68) v2(26.52,96.93) v2(26.52,15.65) v2(27.97,15.62) v2(28.12,29.11) v2(28.12,14.17) v2(29.16,98.86) v2(29.16,97.1) v2(29.36,37.97) v2(29.36,15.62) v2(29.72,14.22) v2(29.95,43.59) v2(30.12,76.53) v2(30.73,49.56) v2(30.81,47.45) v2(30.84,45.69) v2(30.76,44.17) v2(31.17,79.86) v2(31.39,76.56) v2(31.62,98.88) v2(31.62,97.13) v2(31.7,35.79) v2(31.93,41.96) v2(32.41,14.2) v2(33.66,98.96) v2(33.66,97.21) v2(34.09,77.44) v2(34.42,76.07) v2(35.81,98.98) v2(35.81,97.23) v2(36.04,29.26) v2(37.24,29.31) v2(37.95,98.98) v2(37.95,97.23) v2(40.08,98.98) v2(40.08,97.23) v2(40.49,25.76) v2(40.54,23.75) v2(40.51,21.36) v2(42.21,98.98) v2(42.21,97.23) v2(44.35,98.98) v2(44.35,97.23) v2(46.48,98.98) v2(46.48,97.23) v2(48.62,98.98) v2(48.62,97.23) v2(49.63,27.69) v2(50.75,98.98) v2(50.75,97.23) v2(51.26,27.71) v2(52.88,98.98) v2(52.88,97.23) v2(53.04,27.69) v2(55.02,98.98) v2(55.02,97.23) v2(55.45,18.82) v2(55.47,17.27) v2(55.58,15.65) v2(55.96,22.68) v2(56.01,8.36) v2(56.26,19.86) v2(56.36,97.21) v2(56.82,6.15) v2(56.95,3.38) v2(57.15,98.98) v2(57.4,20.19) v2(57.56,8.38) v2(57.84,18.9) v2(57.86,17.32) v2(57.96,15.52) v2(58.57,98.98) v2(58.57,97.23) v2(60.71,98.98) v2(60.71,97.23) v2(62,9.25) v2(62.81,98.98) v2(62.81,97.23) v2(64.95,98.98) v2(64.95,97.23) v2(66.6,17.93) v2(67.13,98.98) v2(67.13,97.23) v2(67.31,19.35) v2(68.43,18.44) v2(68.45,19.3) v2(68.71,98.98) v2(68.71,97.23) v2(69.09,15.72) v2(69.88,15.67) v2(70.61,16.48) v2(70.92,15.7) v2(71.37,18.01) v2(71.63,35.53) v2(71.63,33.05) v2(72.82,36.88) v2(72.87,18.82) v2(73.63,18.39) v2(73.69,25.55) v2(74.02,38.56) v2(73.96,35.38) v2(73.96,24.46) v2(74.35,18.87) v2(74.42,25.55) v2(74.42,18.11) v2(74.55,99.24) v2(74.63,93.7) v2(76.15,89.61) v2(77.77,99.21) v2(77.77,9.65) v2(77.9,85.5) v2(77.93,16.81) v2(77.93,15.77) v2(78.03,93.75) v2(79.65,8.66) v2(80.67,9.5) v2(84.4,29.67) v2(84.35,28.27) v2(85.17,97.21) v2(85.24,6.93) v2(85.27,98.86) v2(86.82,97.28) v2(86.92,98.93) v2(87.1,40.08) v2(87.53,27.13) v2(87.63,39.42) v2(88.65,28.35) v2(88.67,97.28) v2(88.77,98.93) v2(88.8,27.15) v2(88.95,29.34) v2(89.26,26.39) v2(90.07,26.67) v2(90.63,97.28) v2(90.73,98.93) v2(92.41,20.17) v2(92.46,31.93) v2(92.94,30.61) v2(93.17,22.5) v2(93.27,97.46) v2(93.32,23.11) v2(93.37,99.11) v2(93.7,28.88) v2(95.22,31.72) v2(95.22,30.61) v2(95.3,29.69) v2(95.73,97.49) v2(95.83,99.14) v2(96.11,32.56) v2(97.76,97.56) v2(97.76,36.25) v2(97.82,34.32) v2(97.82,33.07) v2(97.84,31.67) v2(97.87,99.21) v2(97.99,23.57) v2(98.17,19.91) v2(99.42,19.89) v2(99.92,97.59) v2(100.03,99.24) v2(100.03,23.6) v2(100.36,19.94) v2(101.75,35.56) v2(101.85,34.21) v2(101.85,28.96) v2(101.96,27.18) v2(102.06,97.59) v2(102.16,99.24) v2(103,34.26) v2(103.12,27.91) v2(103.43,29.34) v2(104.19,97.59) v2(104.29,99.24) v2(104.65,32.08) v2(104.75,33.17) v2(105.82,33.17) v2(106.32,97.59) v2(106.43,99.24) v2(106.53,31.98) v2(107.67,32.99) v2(107.77,5.05) v2(108.23,31.98) v2(108.46,97.59) v2(108.56,99.24) v2(110.59,97.59) v2(110.69,99.24) v2(112.73,97.59) v2(112.83,99.24) v2(114.12,5.18) v2(114.3,71.81) v2(114.38,69.95) v2(114.43,67.89) v2(114.43,64.72) v2(114.45,66.14) v2(114.86,97.59) v2(114.96,99.24) v2(115.95,71.78) v2(116.99,97.59) v2(117.09,99.24) v2(117.75,71.81) v2(119.13,97.59) v2(119.23,99.24) v2(119.53,75.69) v2(120.19,50.32) v2(120.37,52.81) v2(120.57,46) v2(120.95,4.67) v2(121.26,97.59) v2(121.36,99.24) v2(122.12,72.26) v2(122.68,97.59) v2(122.68,46.66) v2(122.78,99.24) v2(122.81,54.46) v2(122.81,52.73) v2(122.96,47.7) v2(123.34,37.49) v2(123.95,54.46) v2(124.1,47.8) v2(124.66,37.49) v2(124.66,36.53) v2(124.82,97.59) v2(124.92,99.24) v2(125.12,75.62) v2(125.48,17.96) v2(125.73,36.55) v2(126.14,46.3) v2(126.29,5.31) v2(126.92,97.59) v2(127.03,99.24) v2(128.7,72.09) v2(129.06,97.59) v2(129.06,65.05) v2(129.16,99.24) v2(129.67,78.84) v2(130.76,75.59) v2(131.24,97.59) v2(131.34,99.24) v2(132.82,97.59) v2(132.92,99.24) v2(133.2,54.56) v2(133.73,53.98) v2(134.06,17.86) v2(134.21,58.72) v2(134.32,83.9) v2(134.34,54.61) v2(135,35.86) v2(135.13,78.89) v2(135.36,64.95) v2(135.76,50.27) v2(135.79,49.12) v2(135.81,37.62) v2(135.92,43.94) v2(136.47,47.9) v2(136.6,56.41) v2(137.39,88.57) v2(137.92,5.56) v2(138.58,37.69) v2(138.81,47.78) v2(139.04,48.79) v2(139.24,50.7) v2(139.62,46.38) v2(139.85,35.86) v2(140.51,83.72) v2(147.24,88.42) v3(23.9,41.66) v3(23.9,39.67) v6(5.11,25.88) v6(36.98,54.33) v6(76.07,96.42) v6(97.33,4.29) v6(112.88,11.2) v6(118.95,11.33) v6(125.78,80.06) v6(135.13,59.84) v6(147.7,12.22)
